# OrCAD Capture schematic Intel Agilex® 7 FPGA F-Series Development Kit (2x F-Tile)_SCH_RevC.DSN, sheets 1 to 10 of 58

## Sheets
1 PG01 COVER, TOC, NOTES: title: AGILEX FM86/FM76 DEVELOPMENT KIT; rev: C1; note: 180-0330678-C1
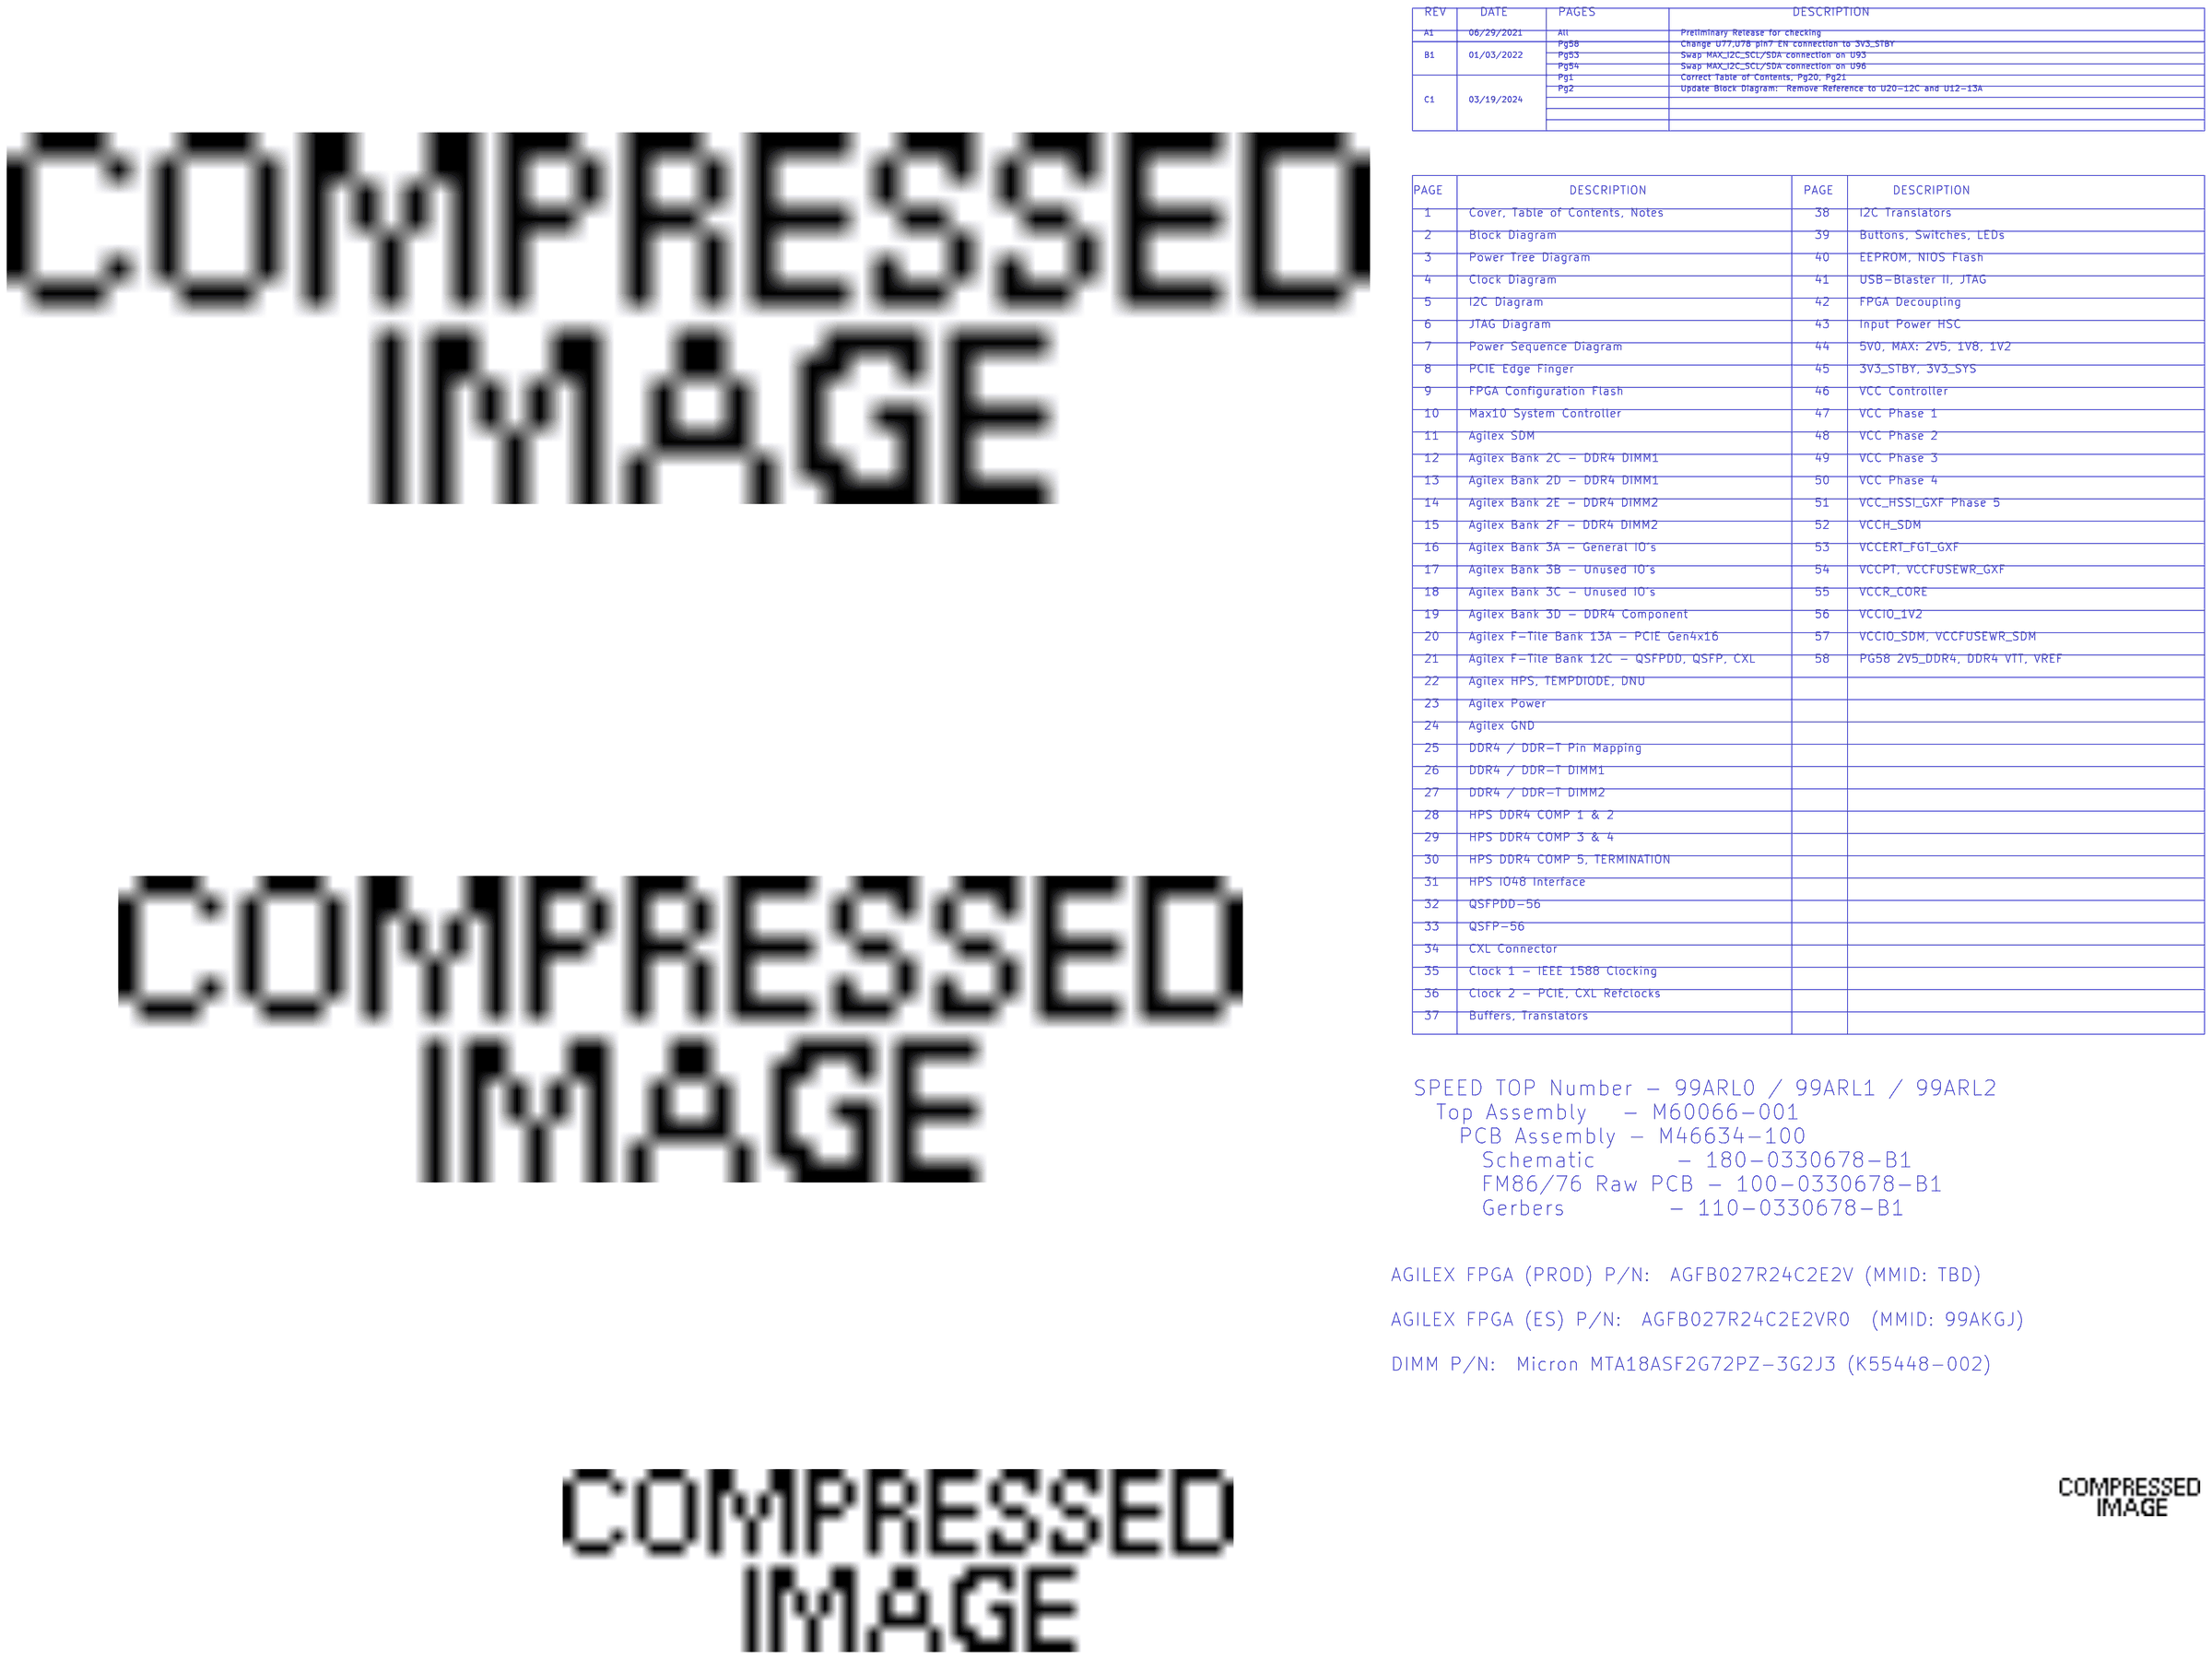
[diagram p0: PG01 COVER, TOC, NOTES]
2 PG02 BLOCK DIAGRAM
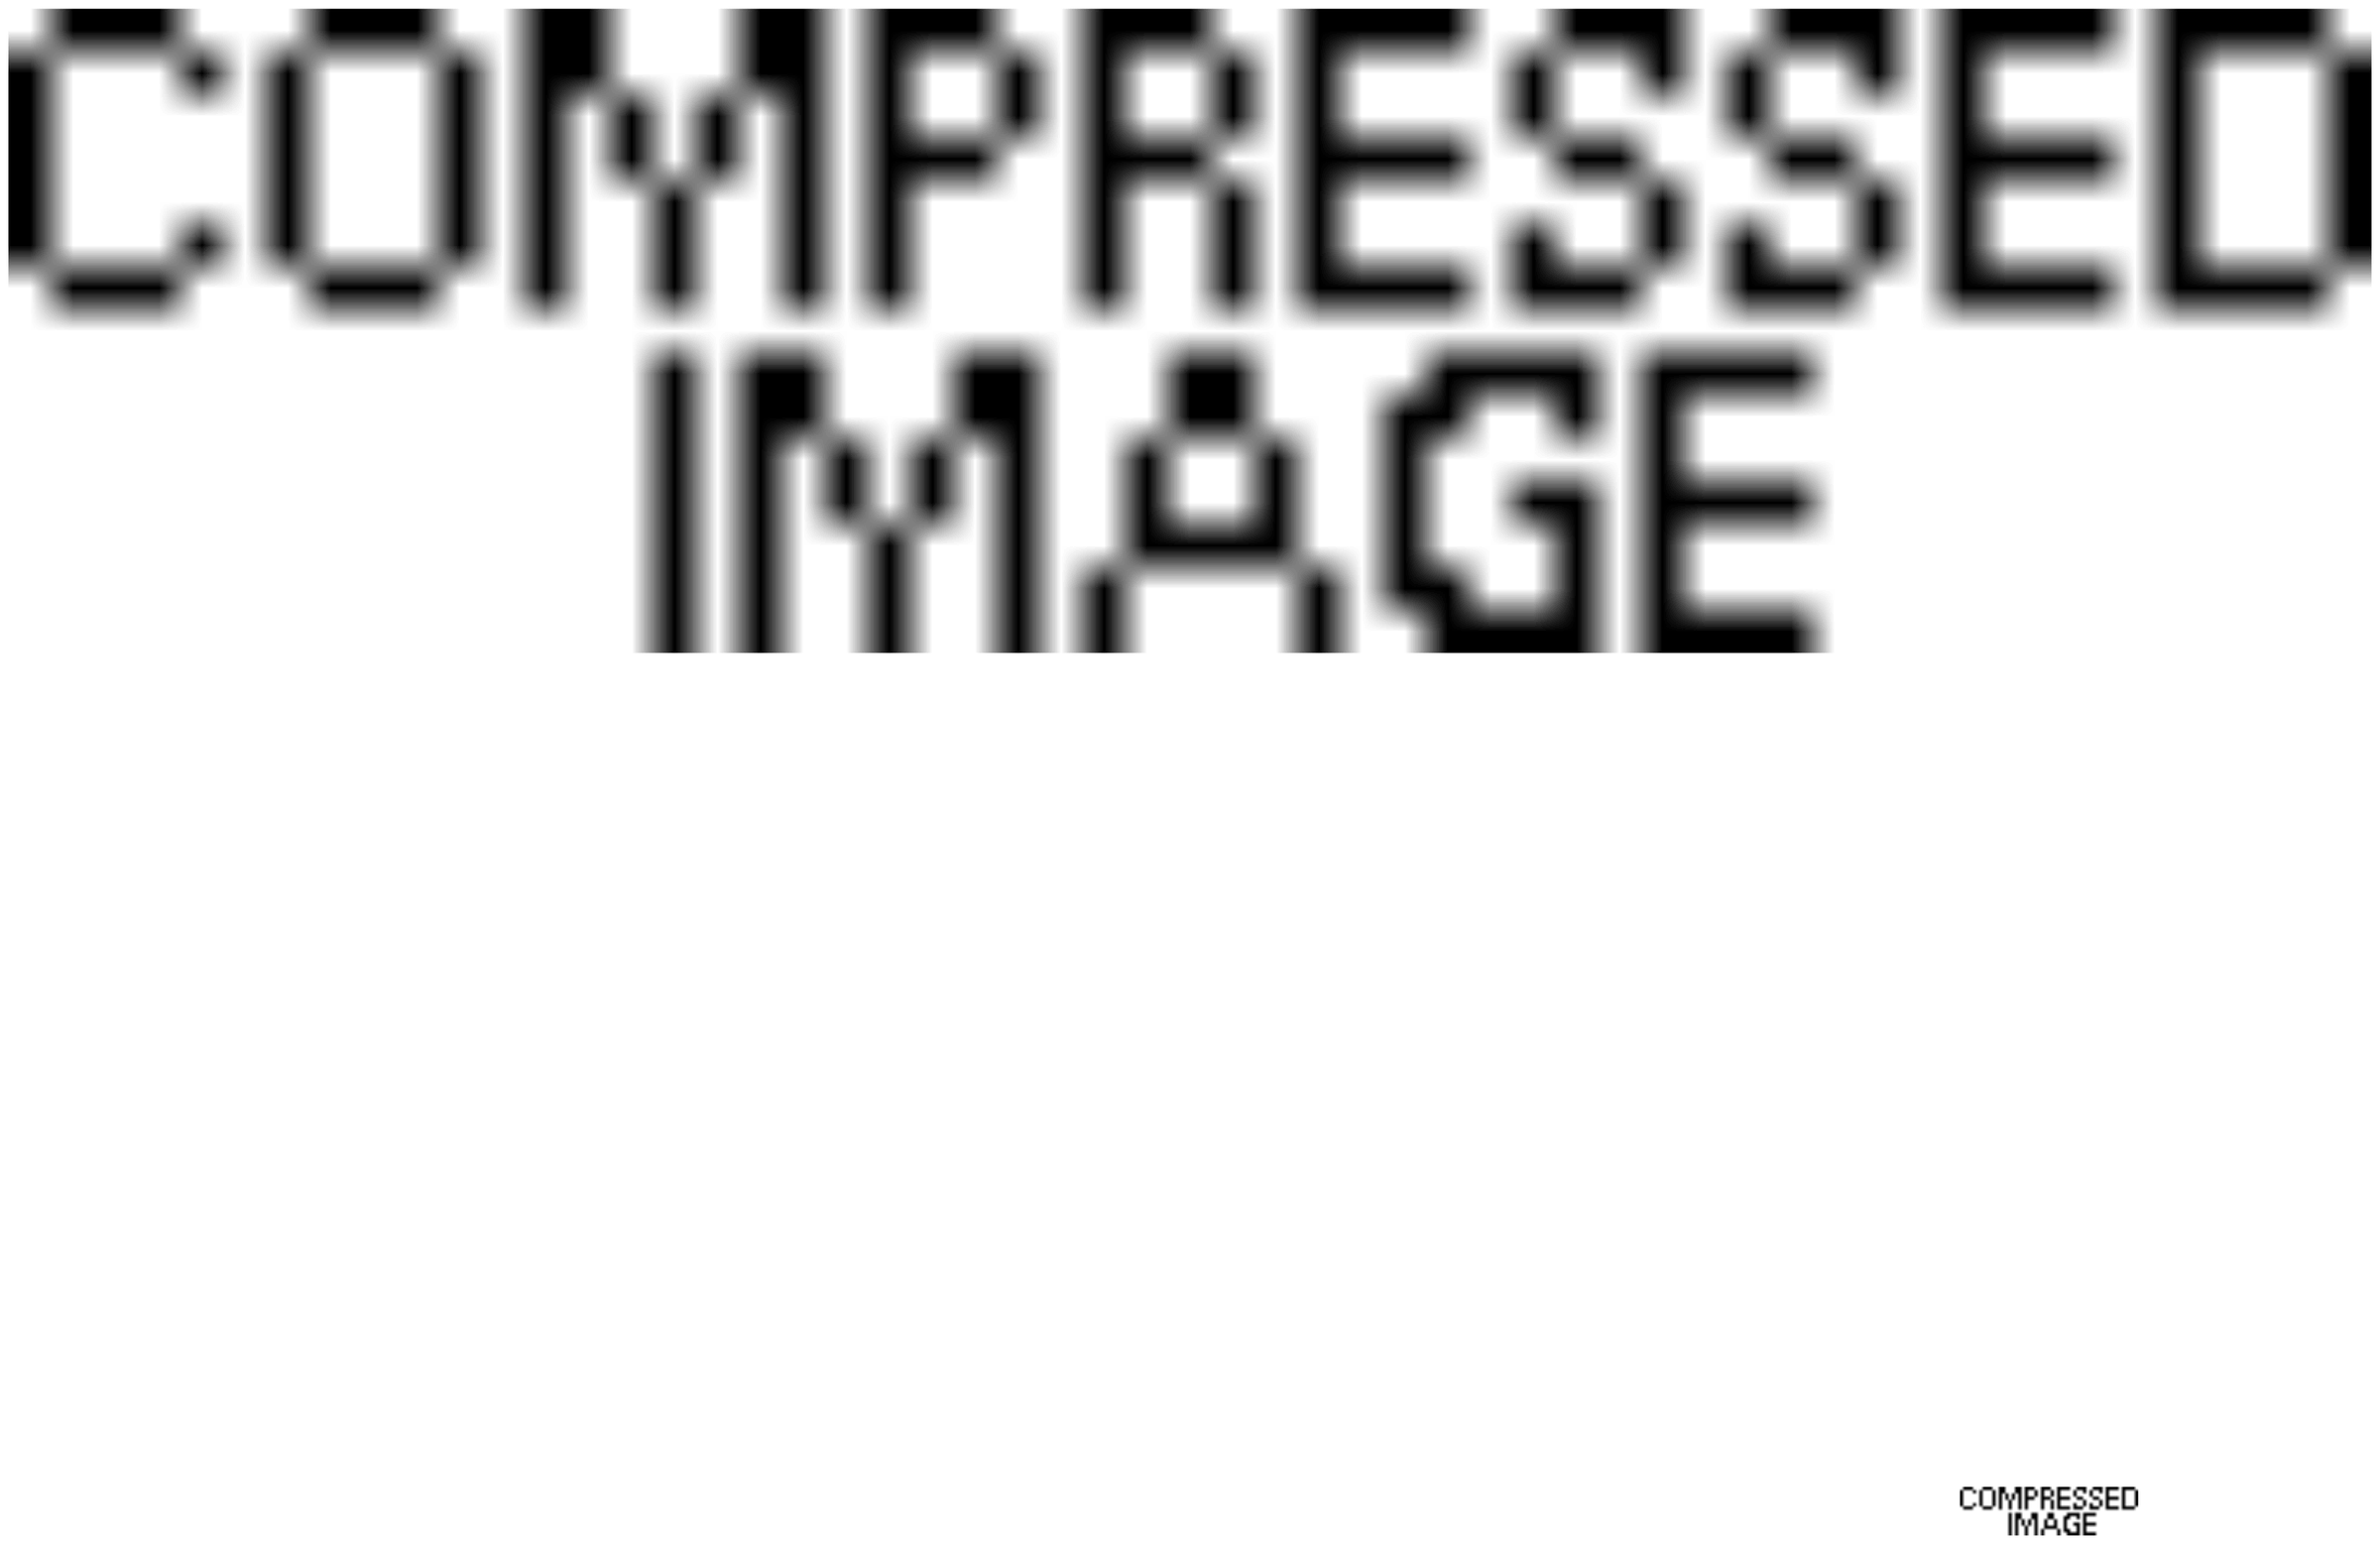
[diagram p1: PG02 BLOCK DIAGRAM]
3 PG03 POWER TREE DIAGRAM
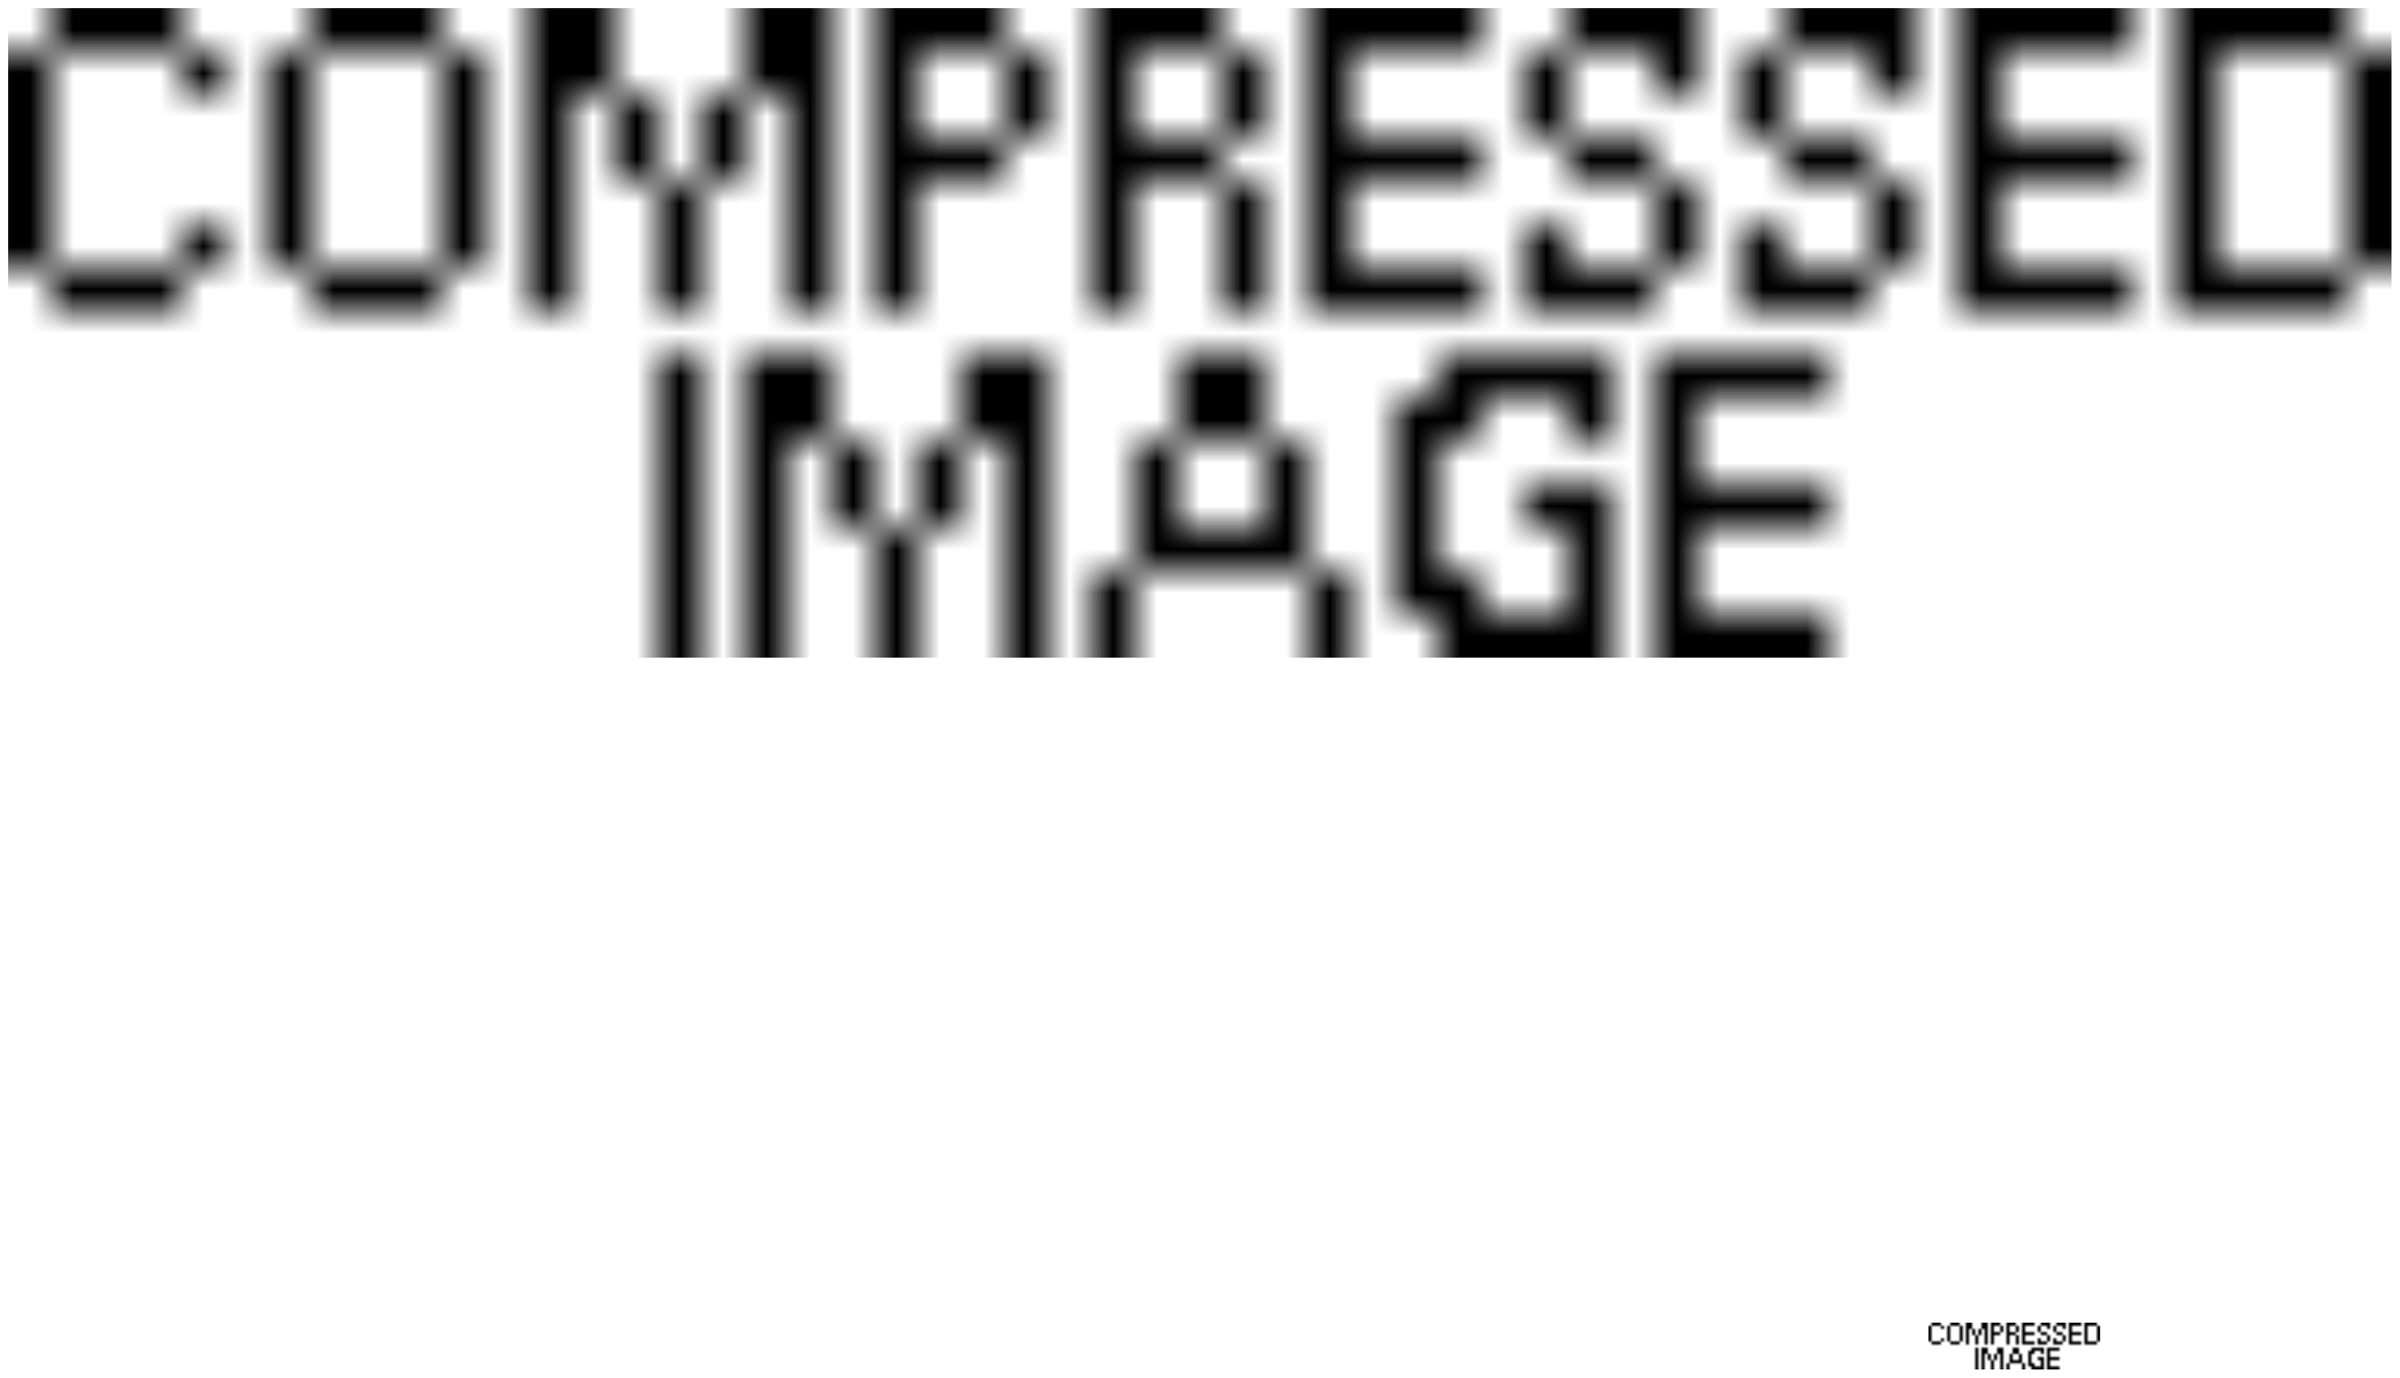
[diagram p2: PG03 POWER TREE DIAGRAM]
4 PG04 CLOCK DIAGRAM
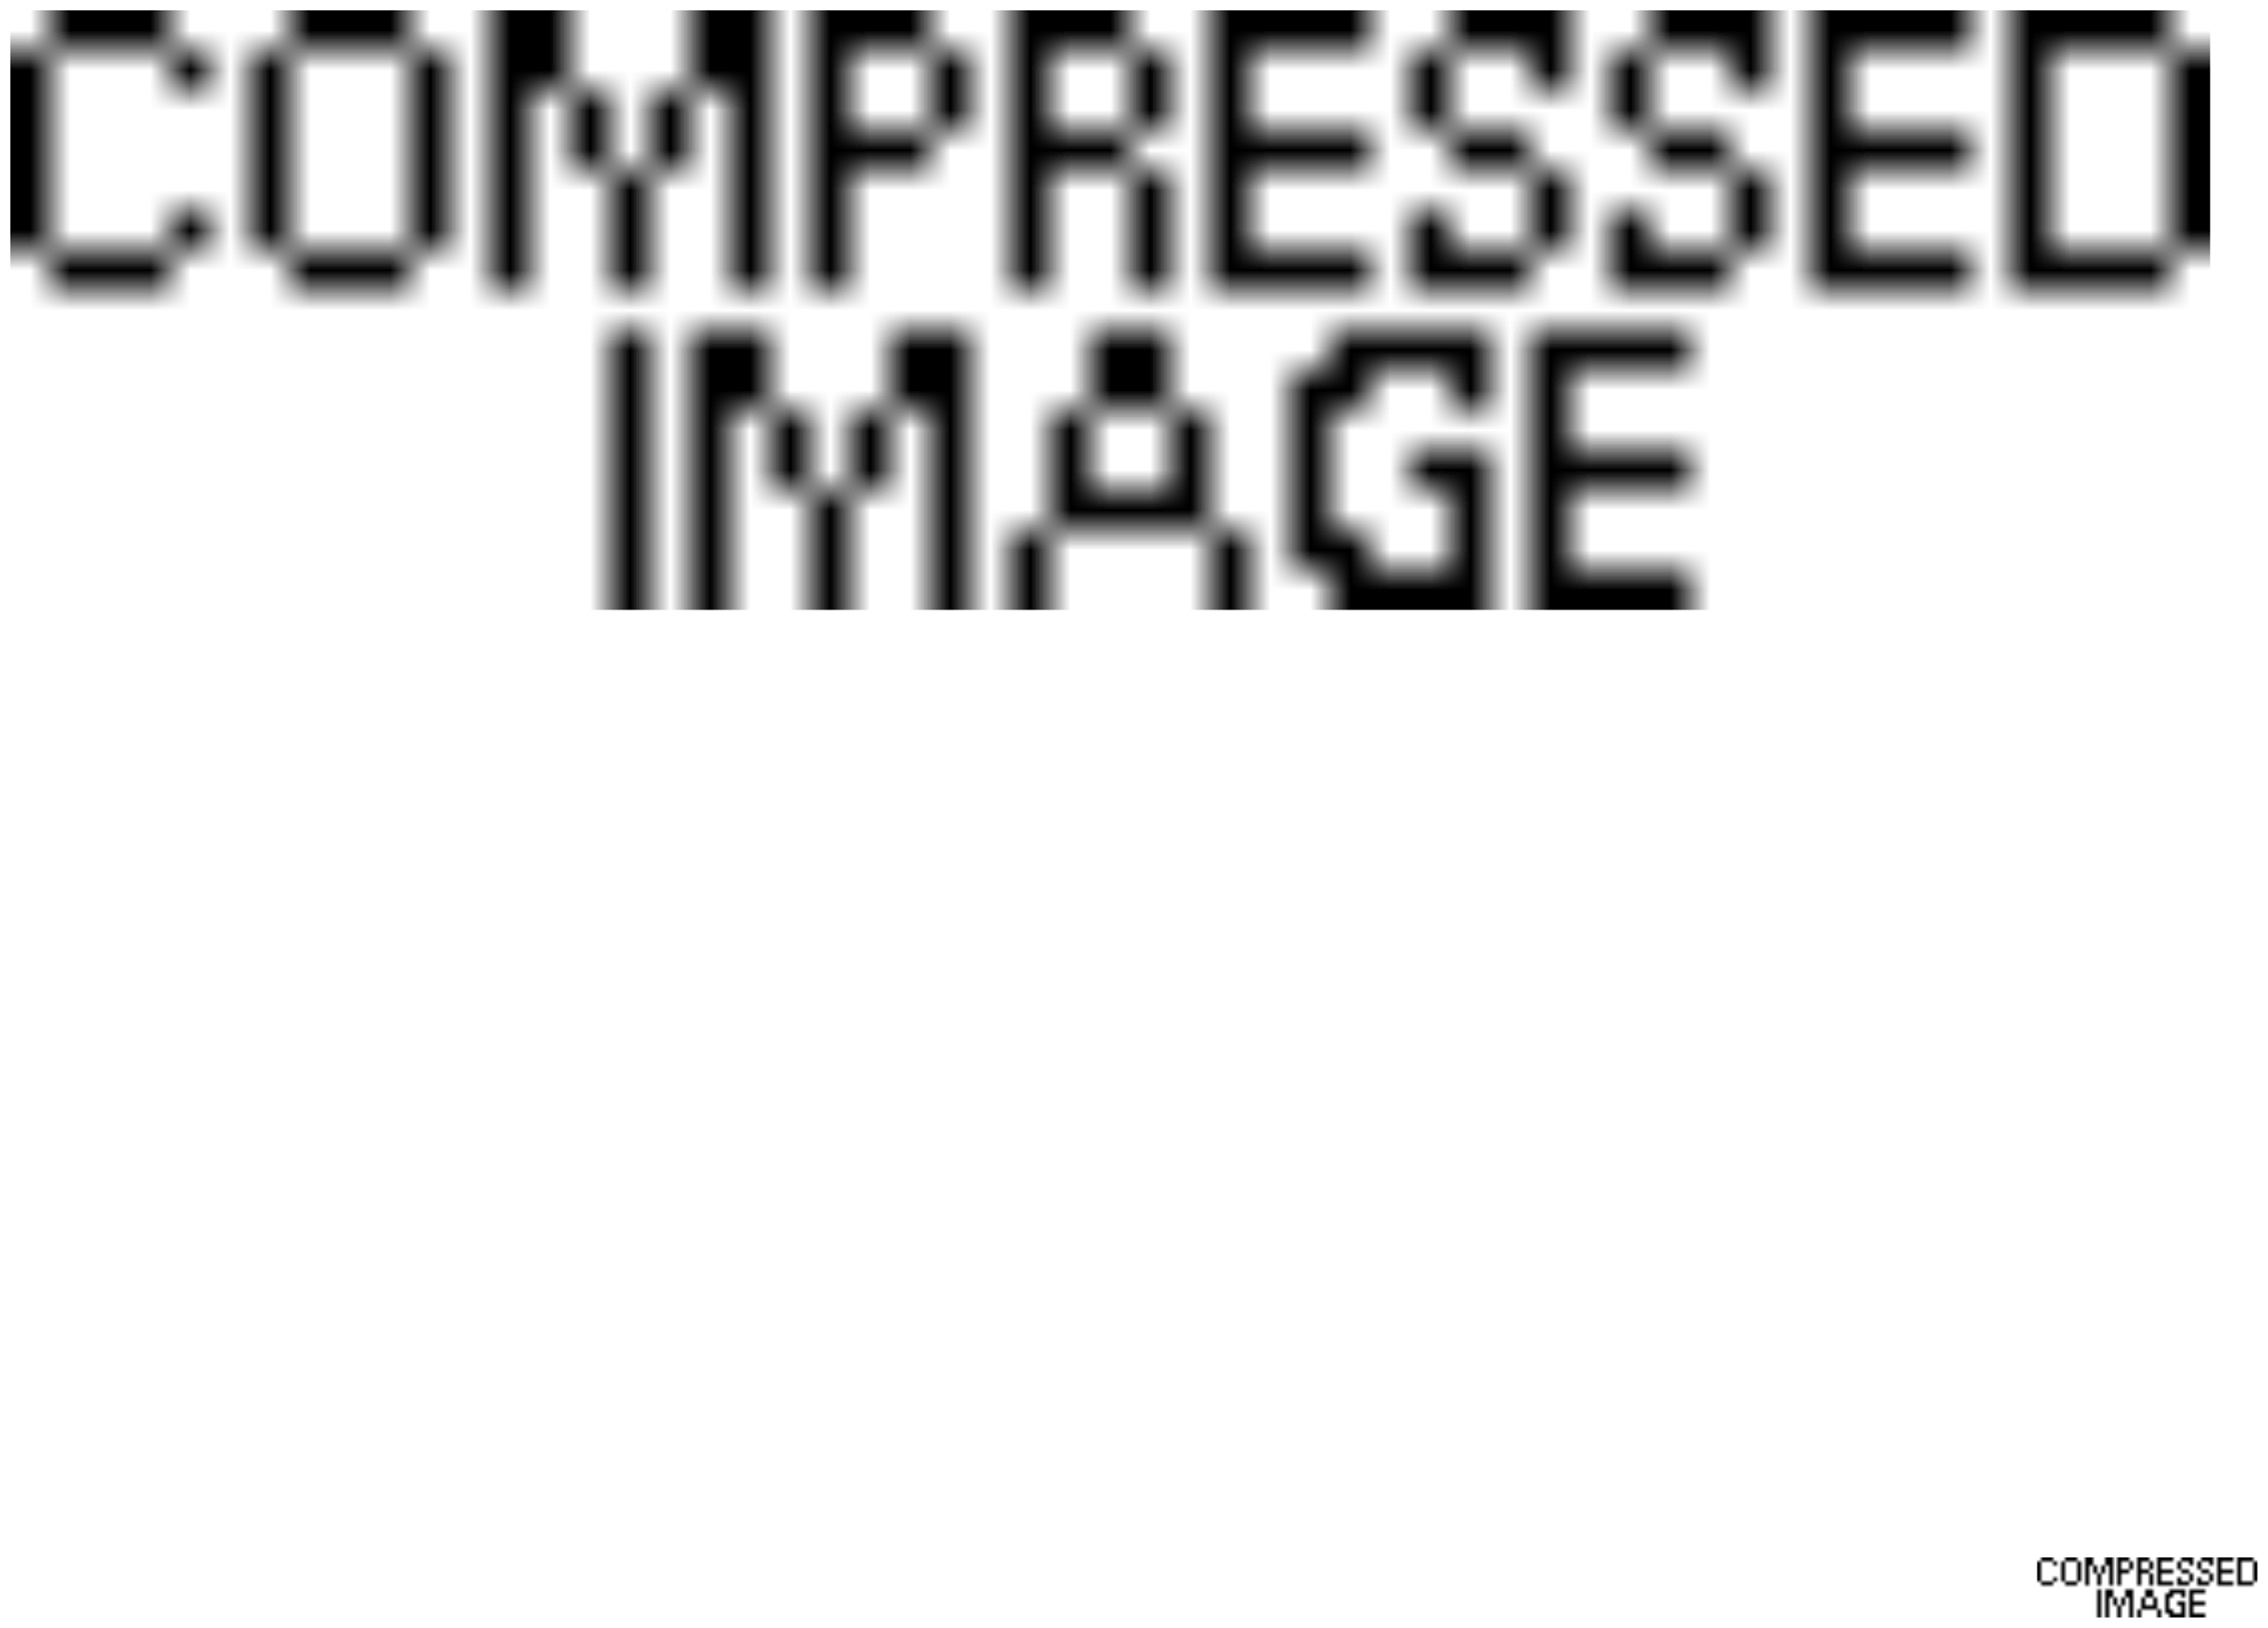
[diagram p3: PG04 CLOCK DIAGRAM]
5 PG05 I2C DIAGRAM
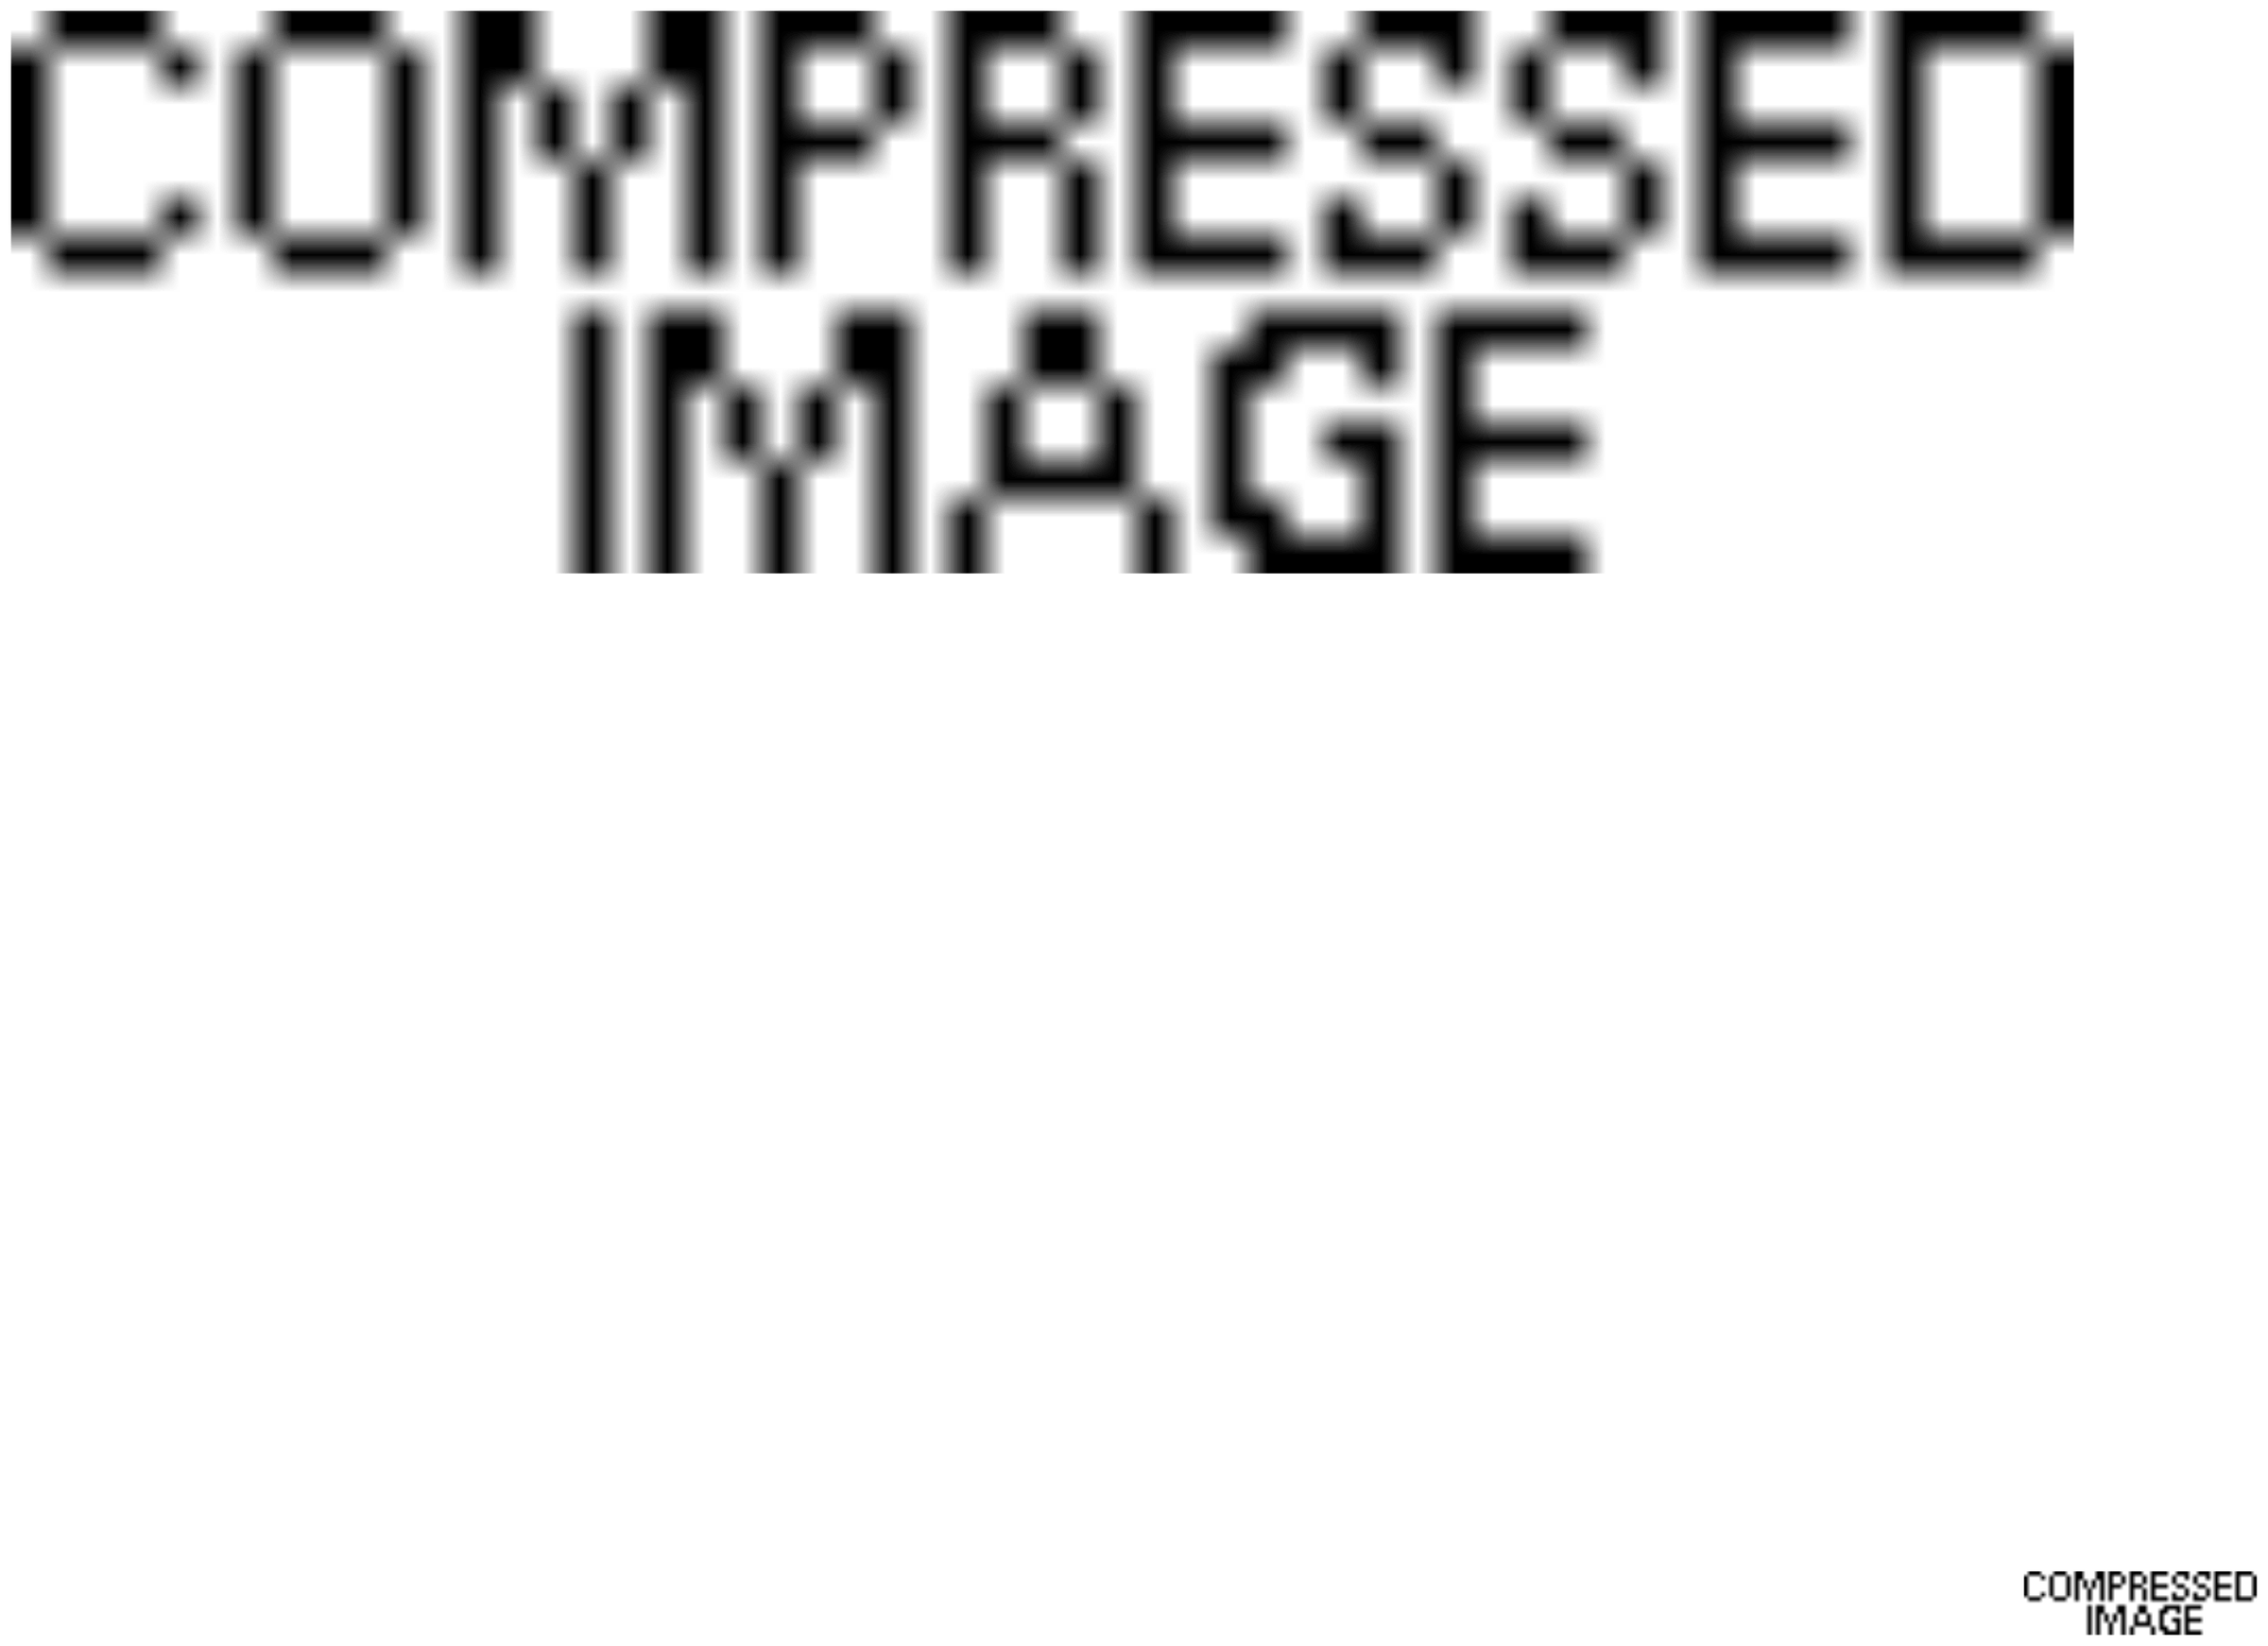
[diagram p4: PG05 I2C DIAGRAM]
6 PG06 JTAG & PCIE RESET DIAGRAM
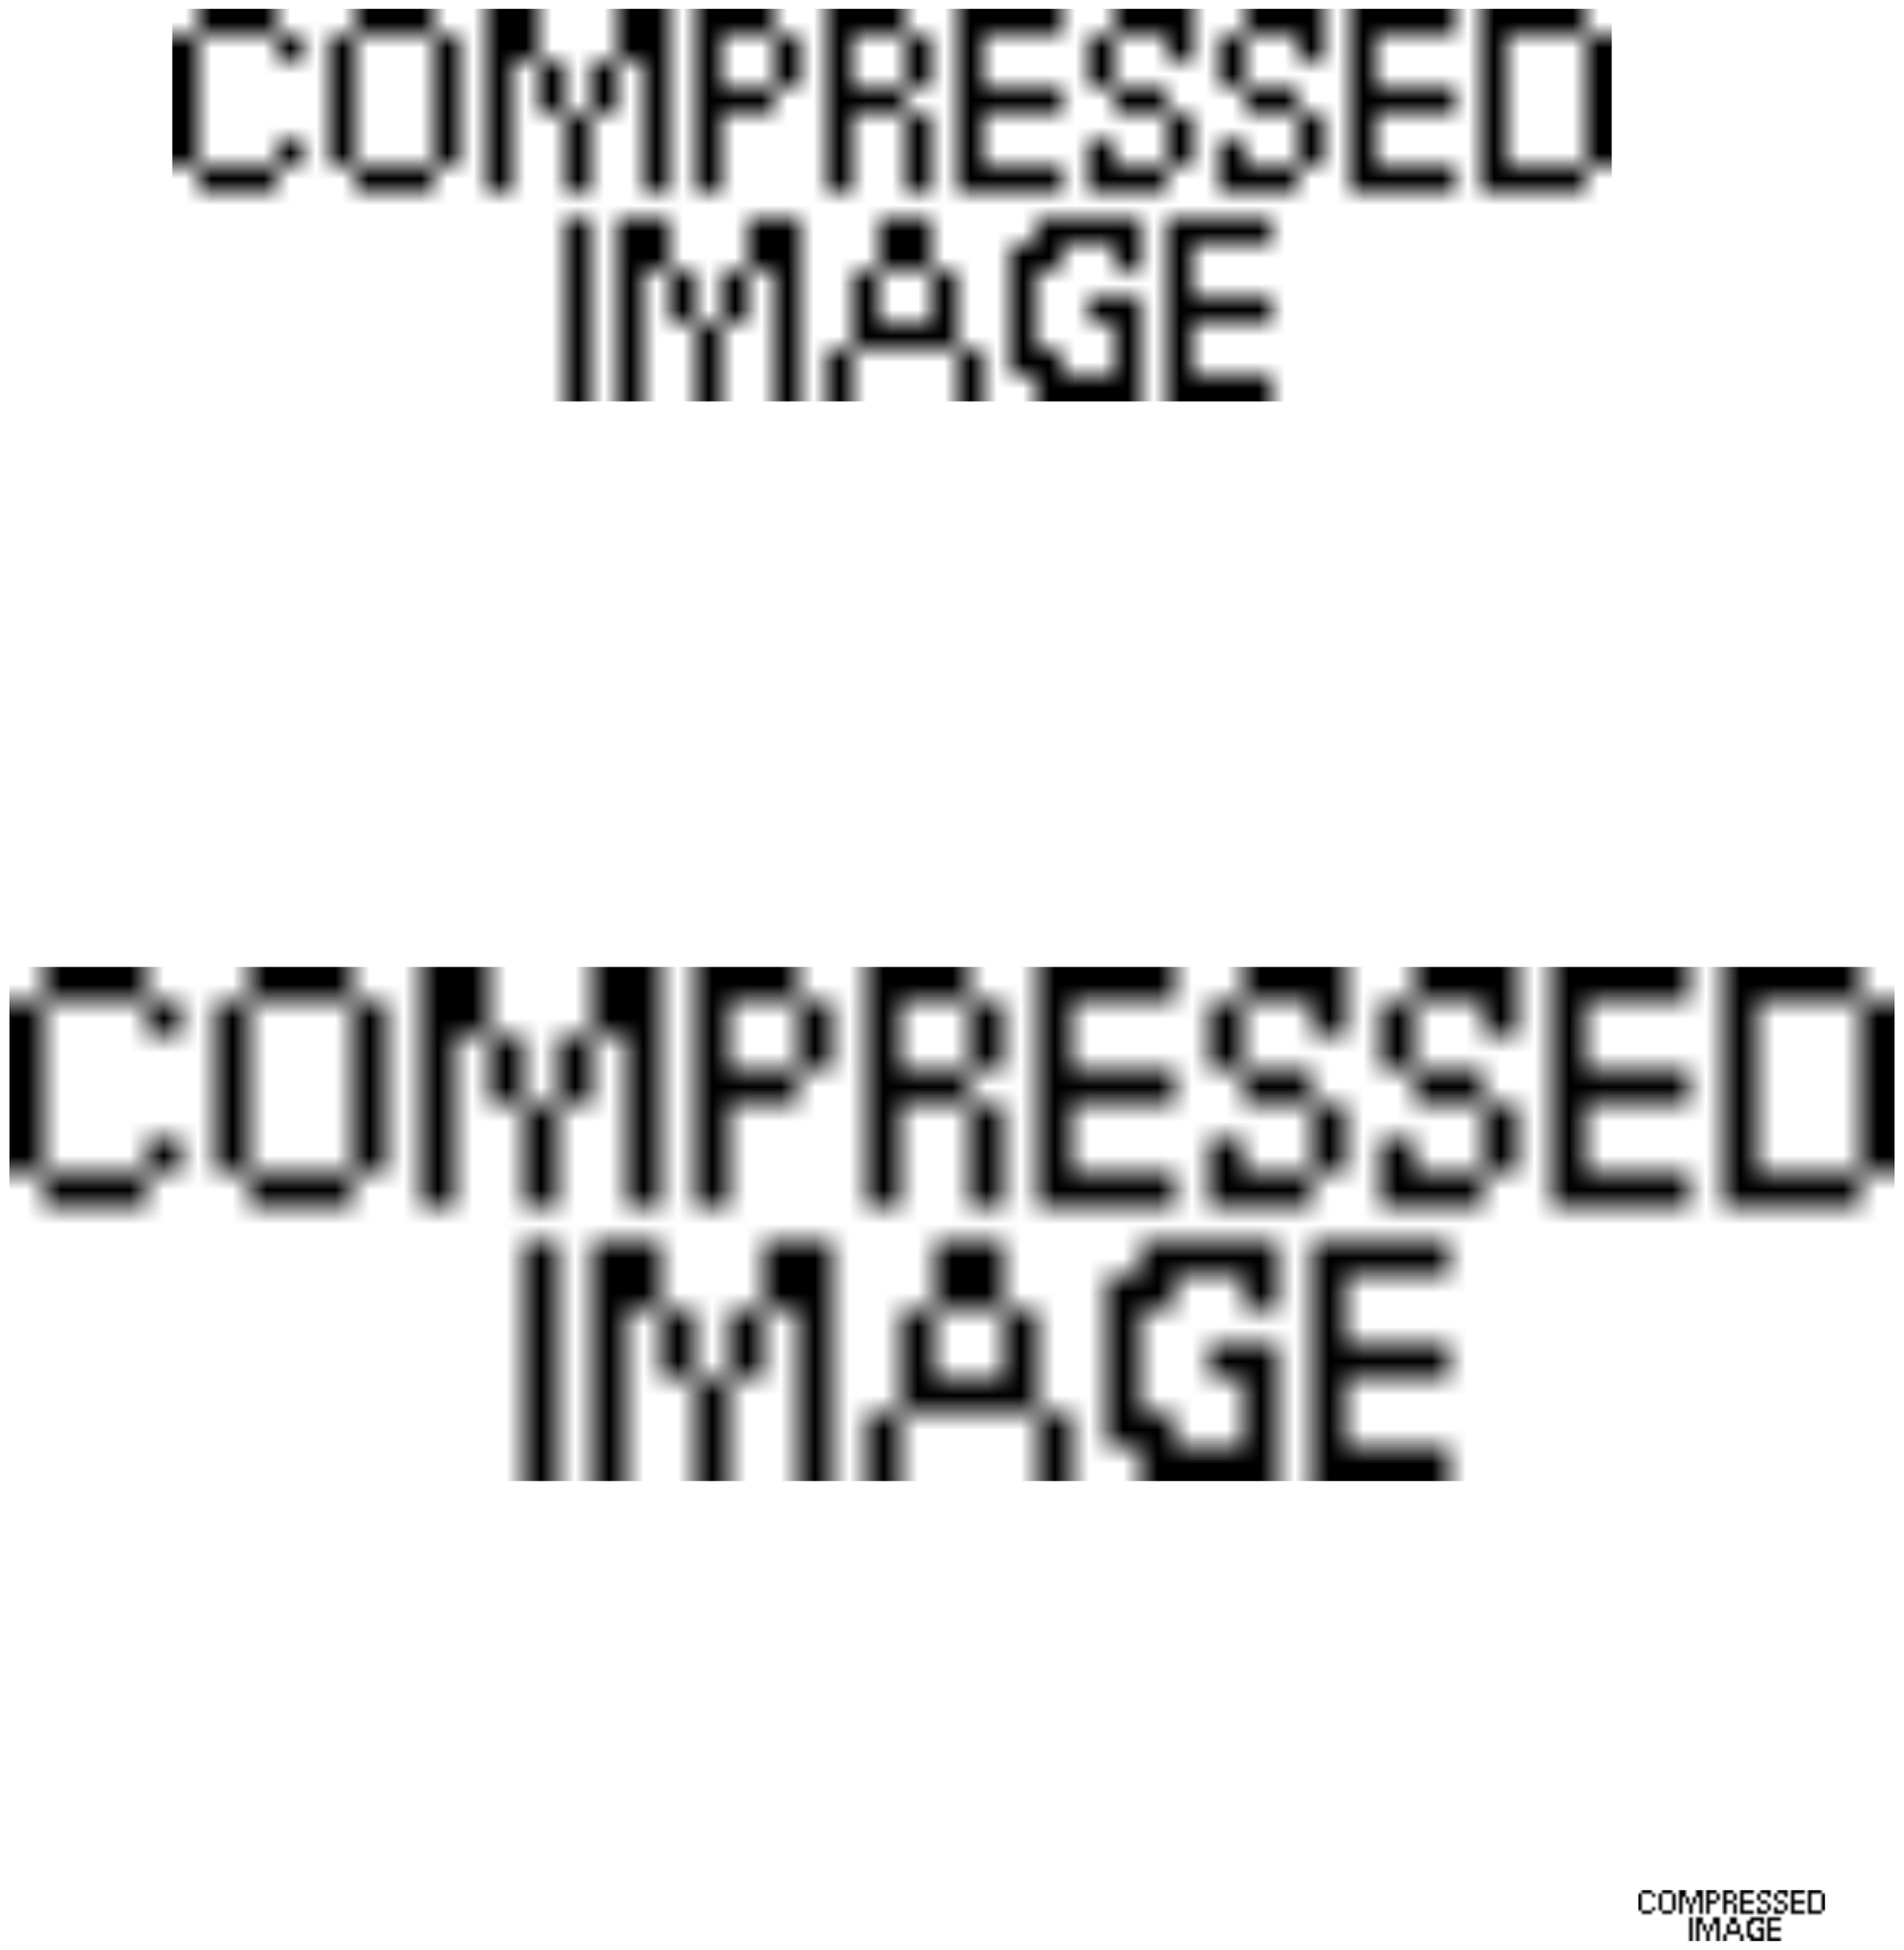
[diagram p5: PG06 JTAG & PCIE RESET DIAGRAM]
7 PG07 MAX10 CONTROLLER DIAGRAM
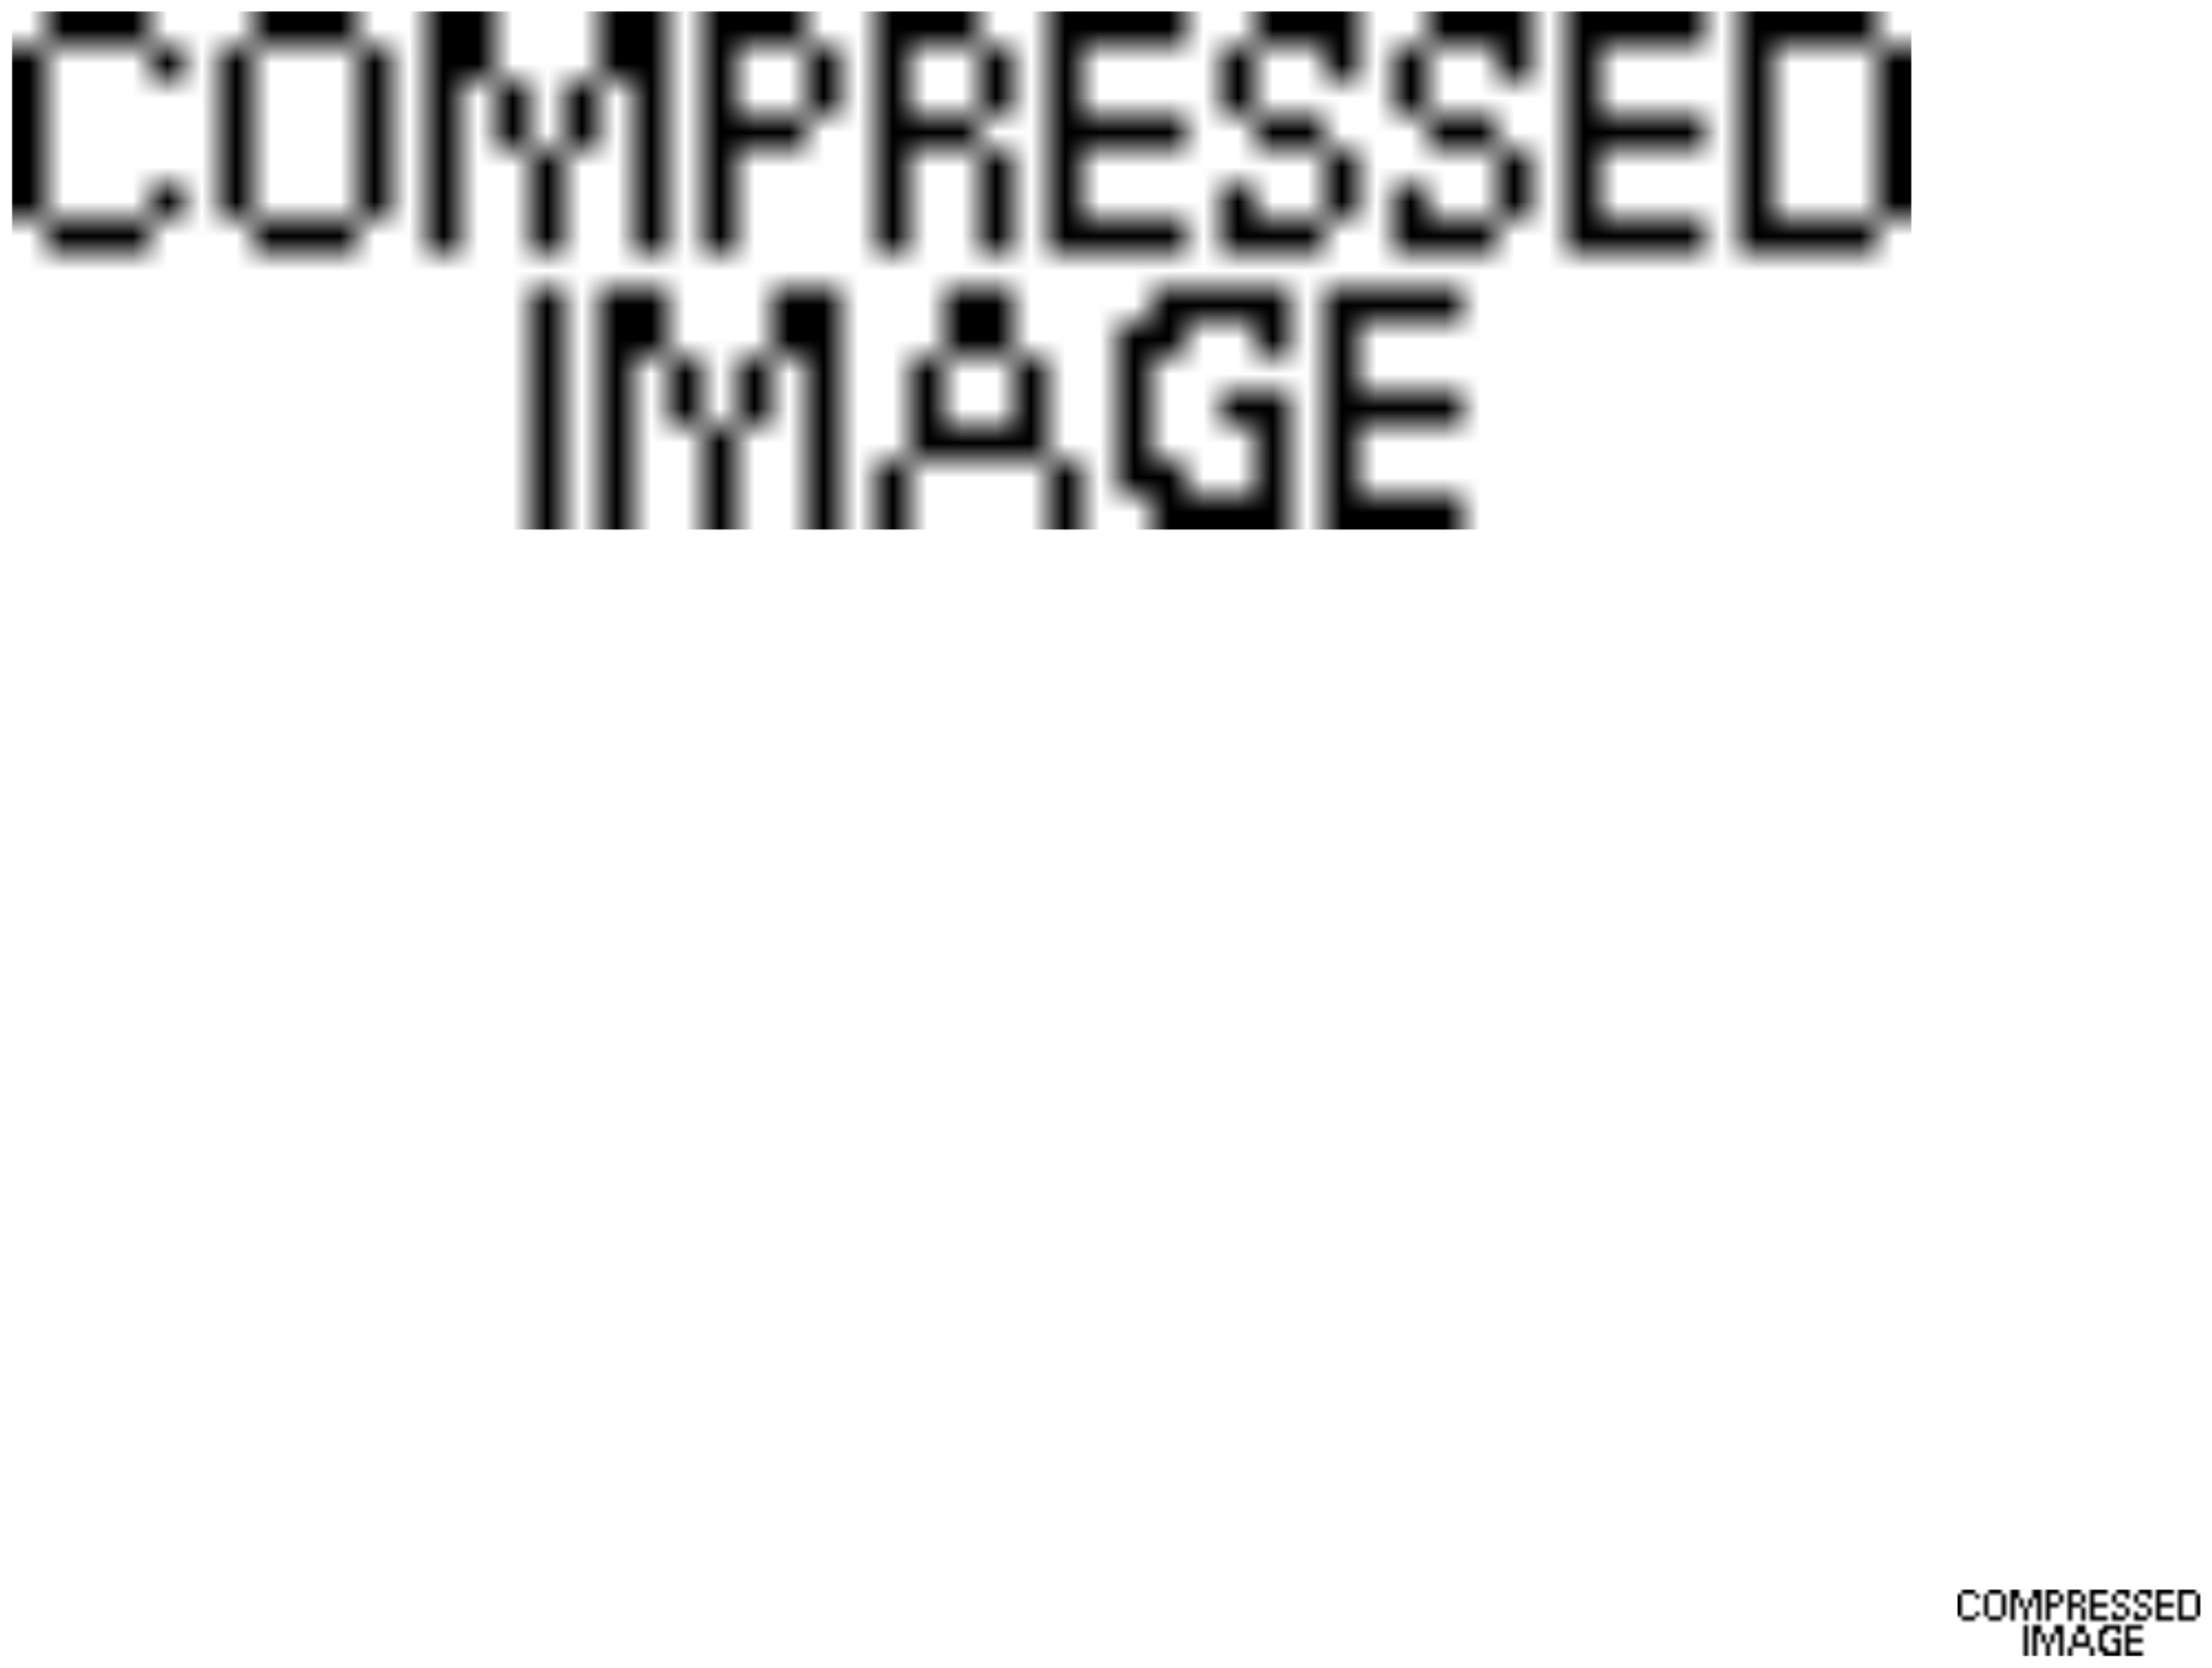
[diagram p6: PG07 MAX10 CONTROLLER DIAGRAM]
8 PG08 PCIE EDGE FINGER: size C
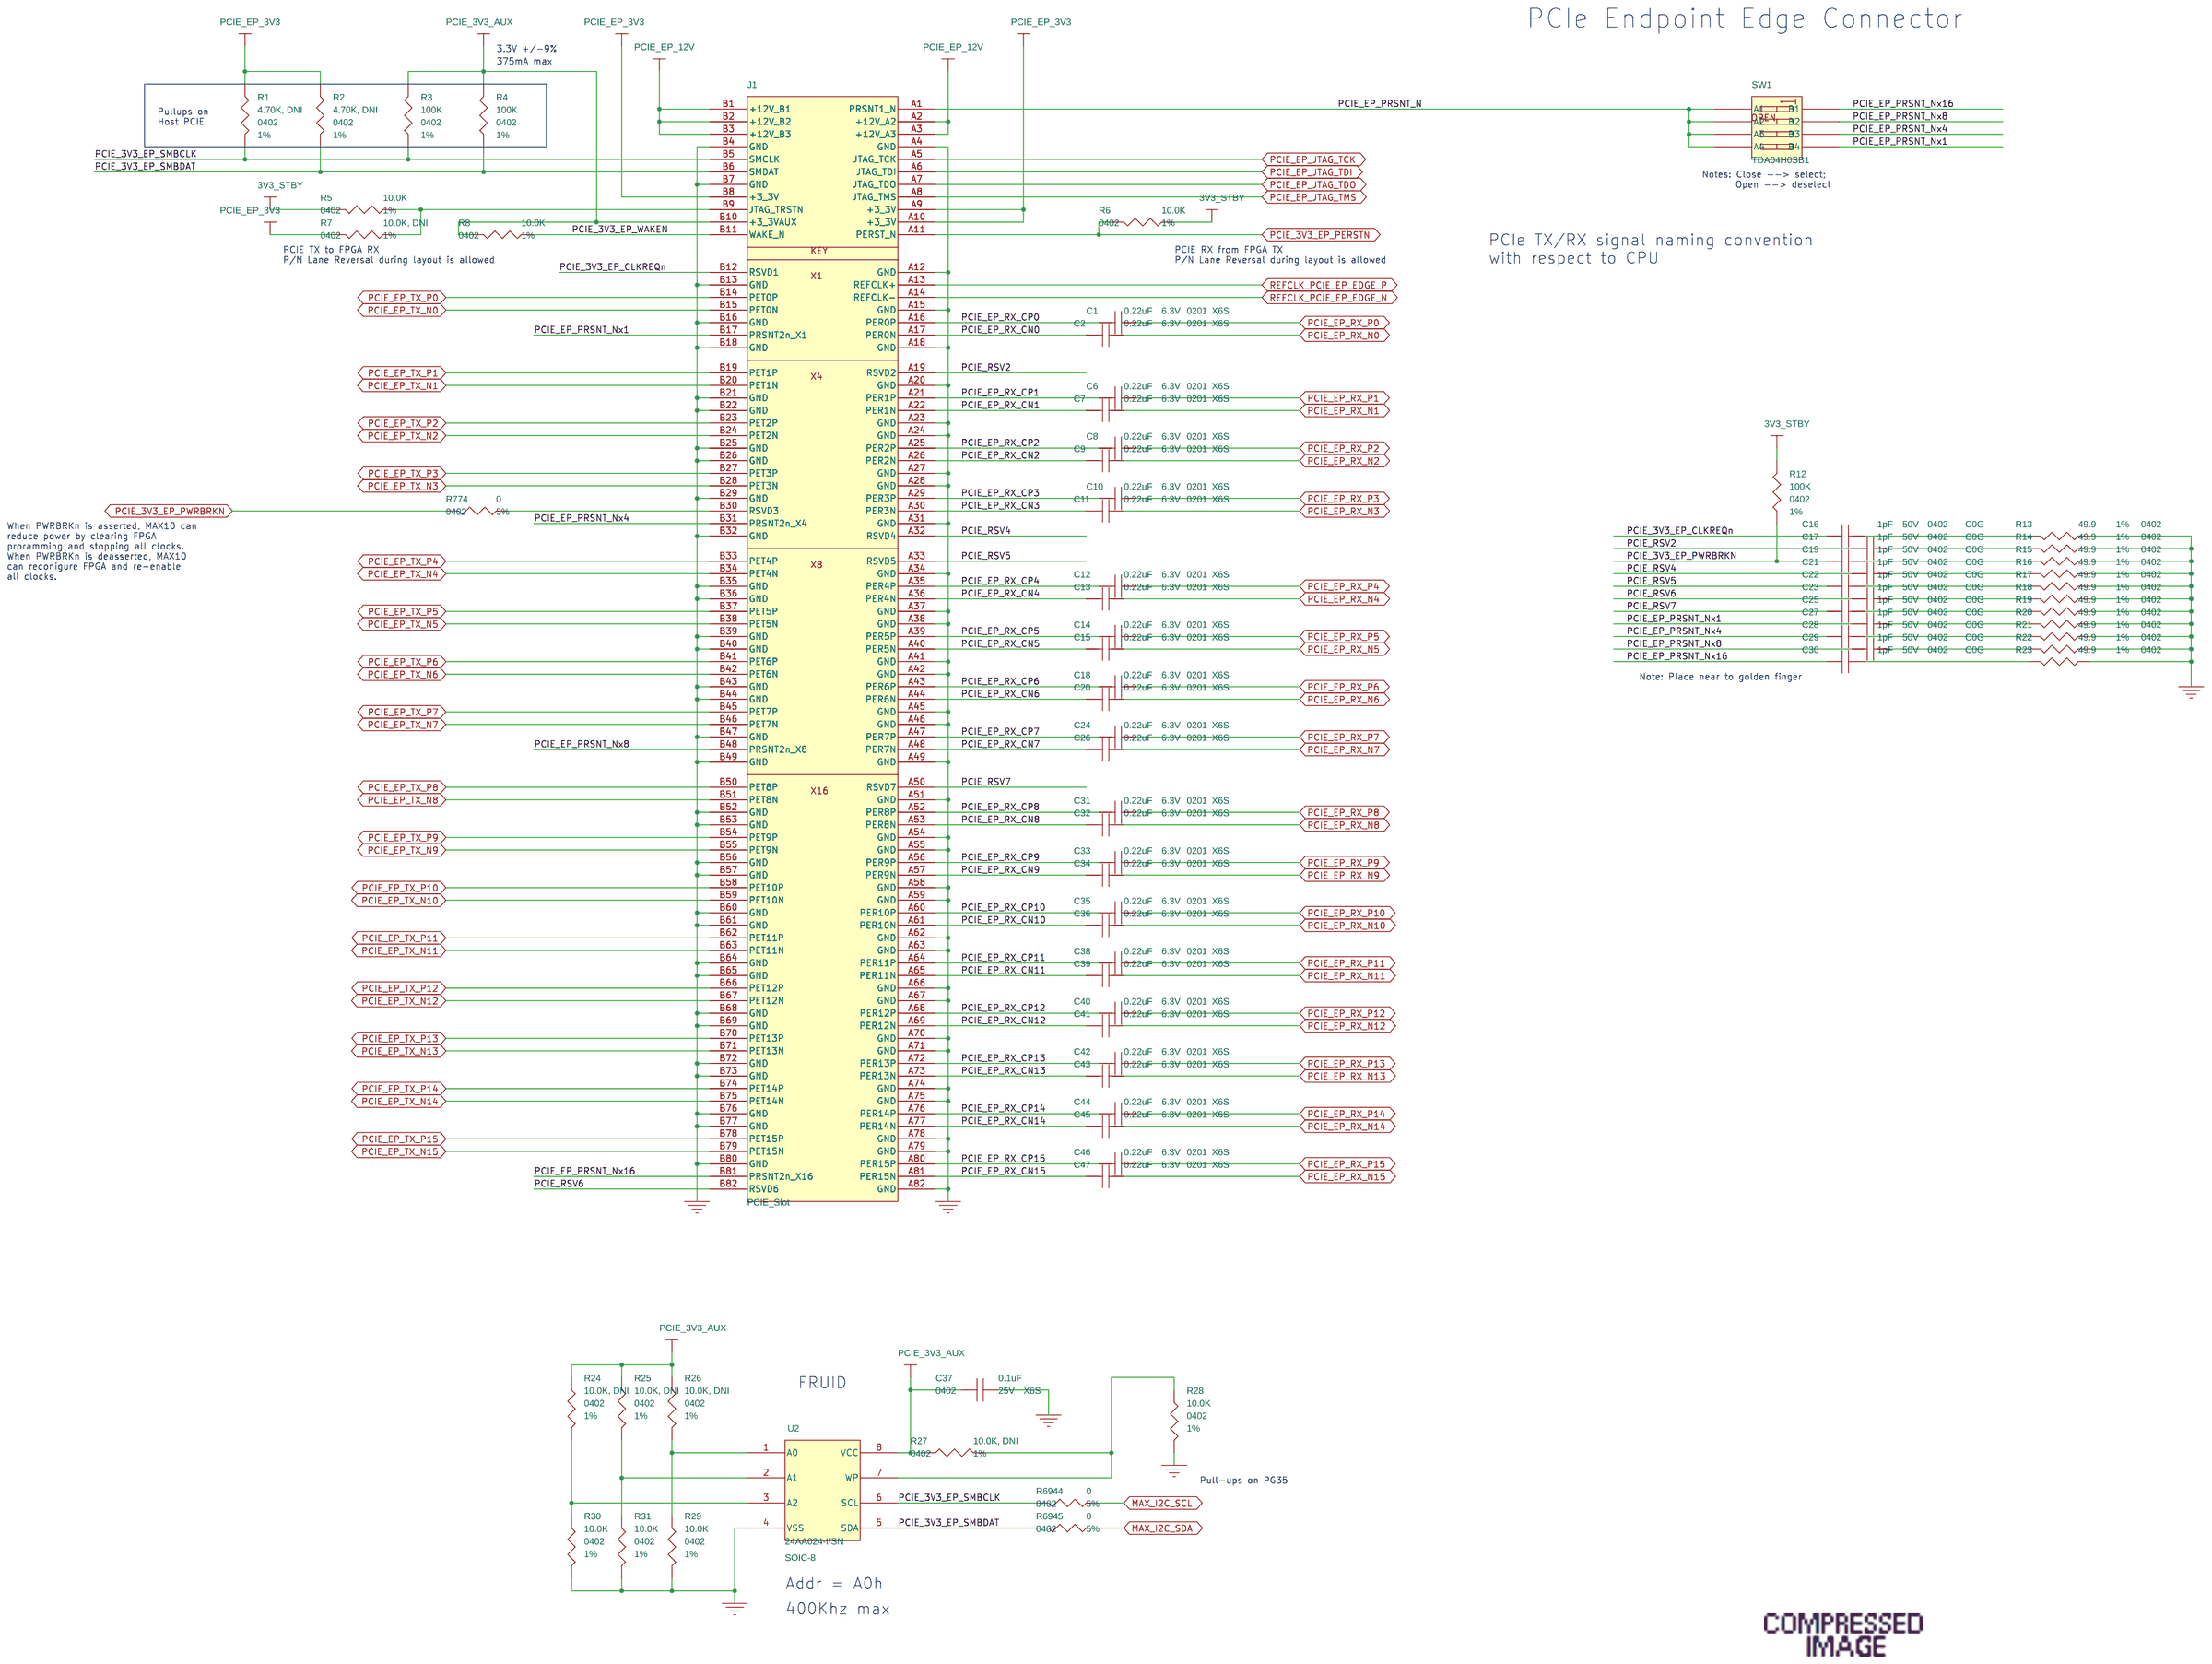
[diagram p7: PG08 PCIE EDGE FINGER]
9 PG09 FPGA CONFIG FLASH: size C
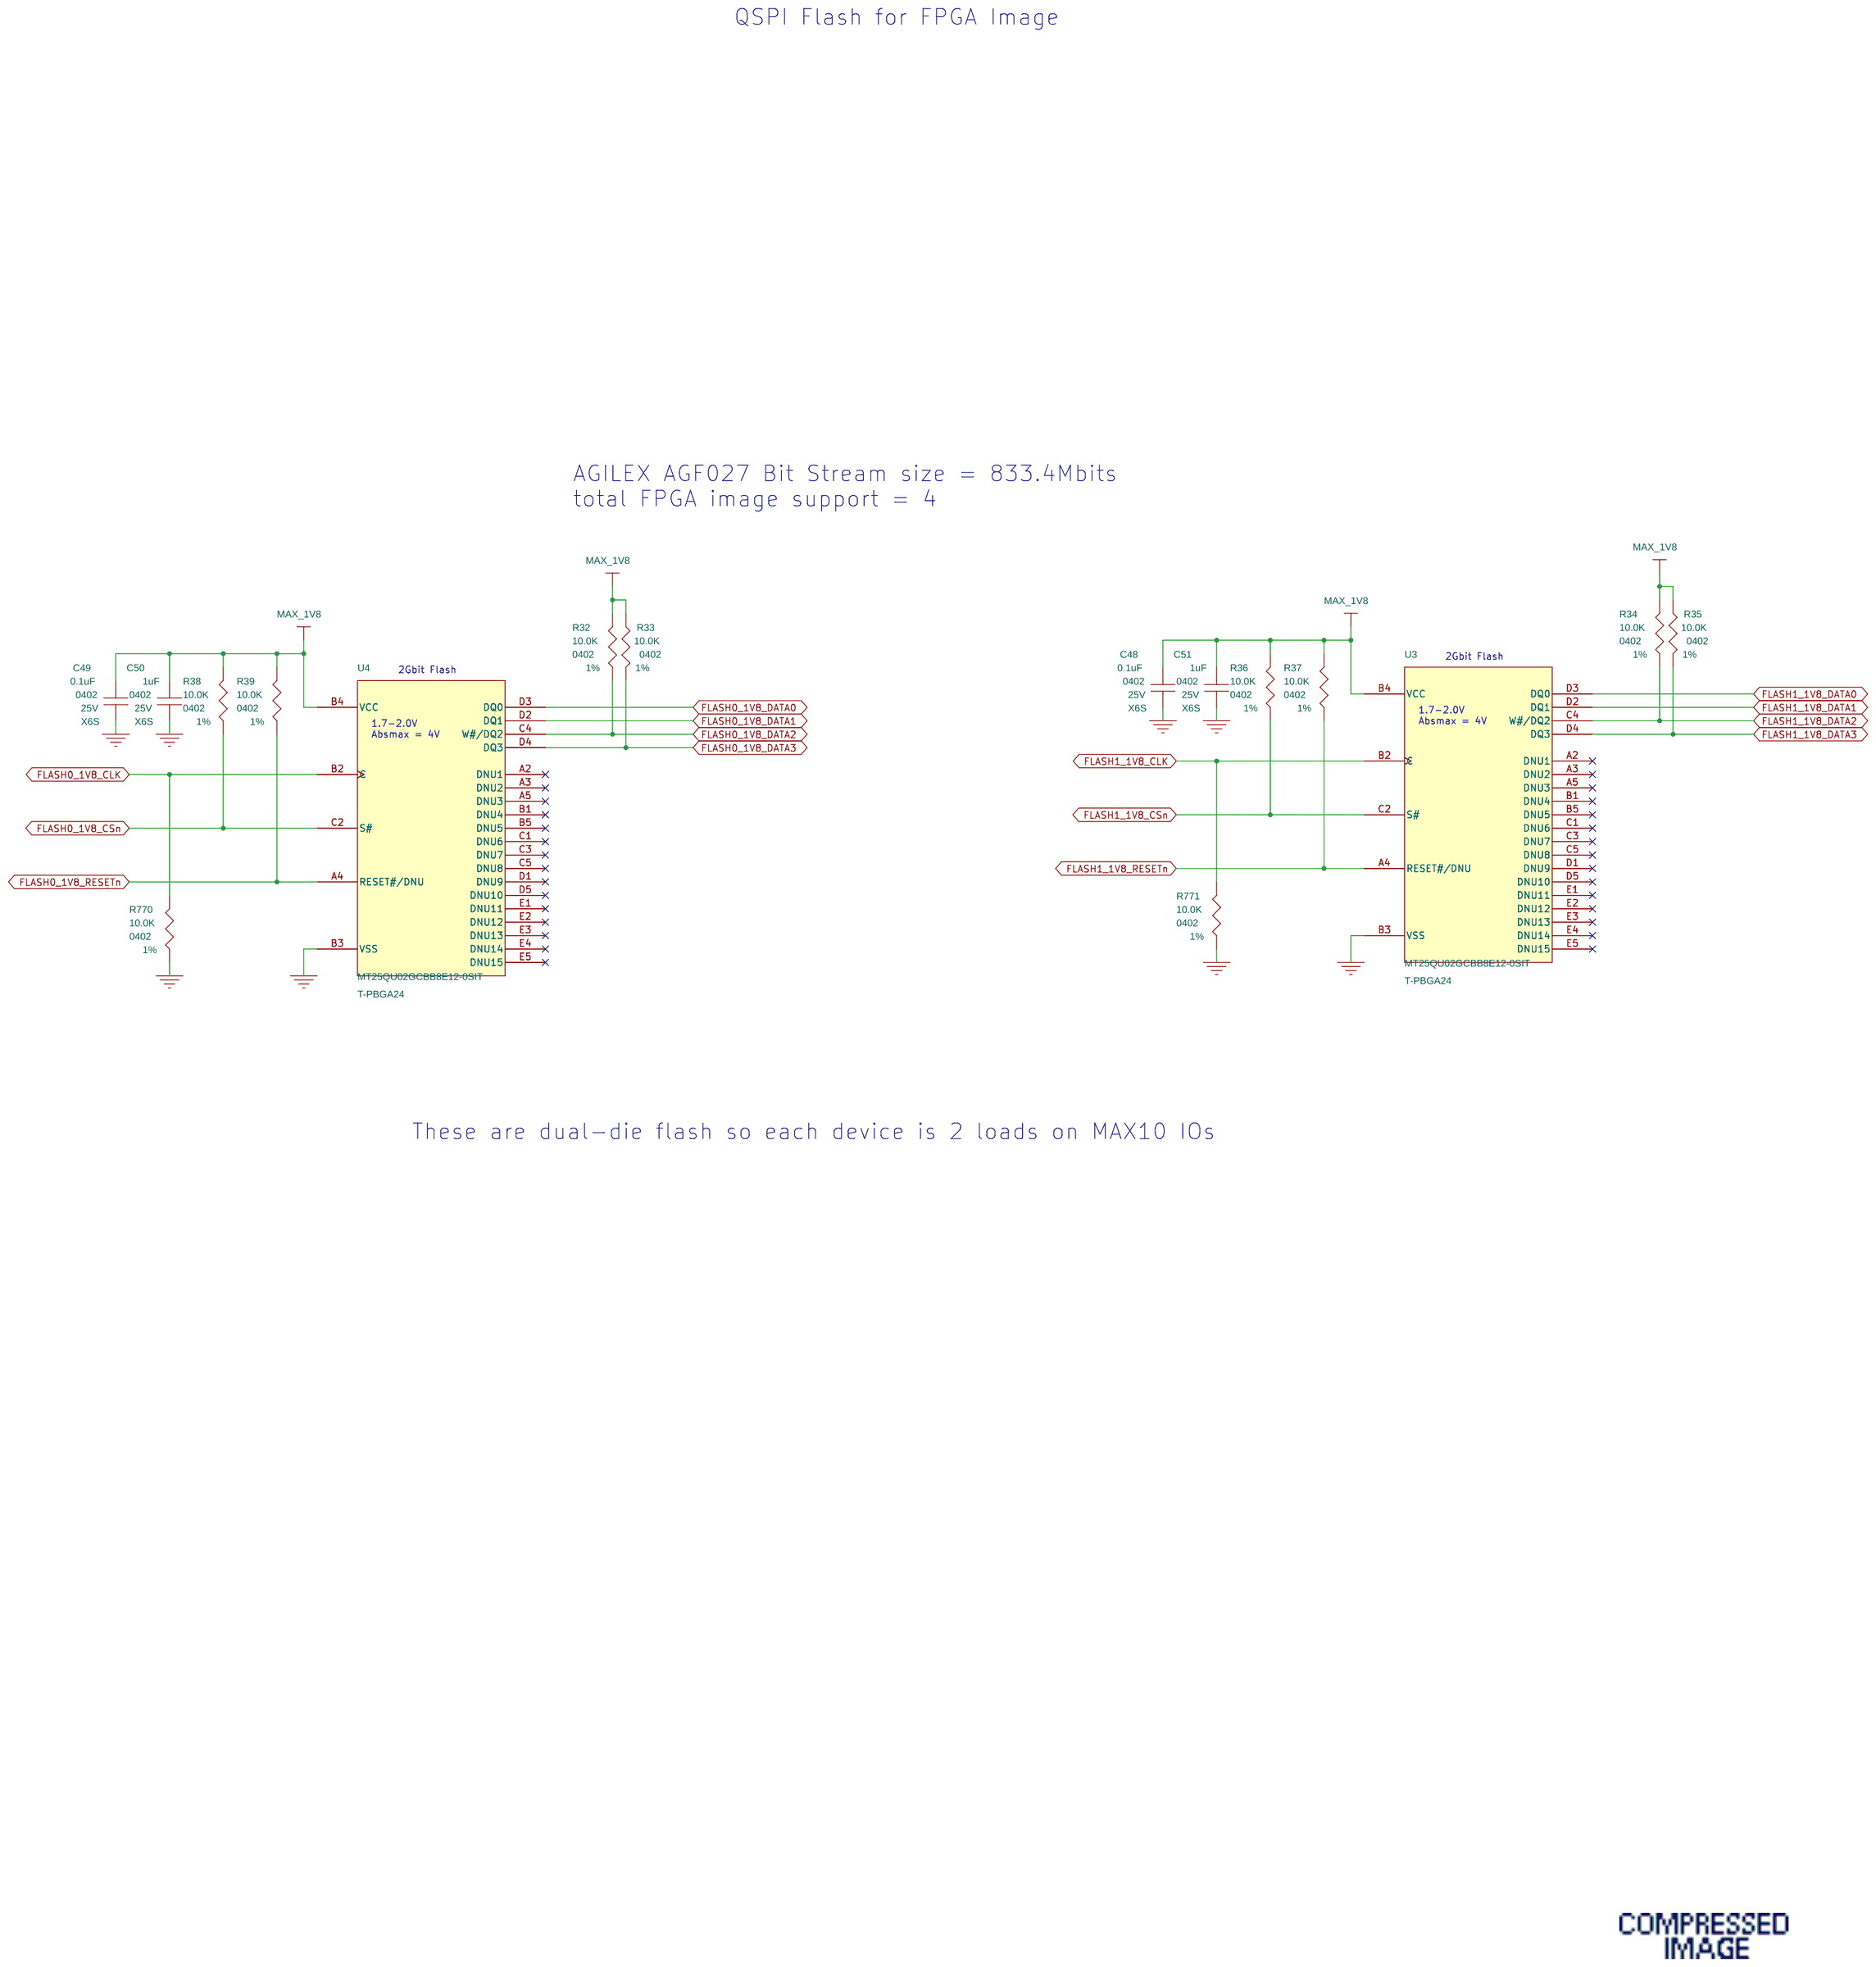
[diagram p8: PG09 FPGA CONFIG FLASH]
10 PG10 MAX10 SYSTEM CTRL: size C
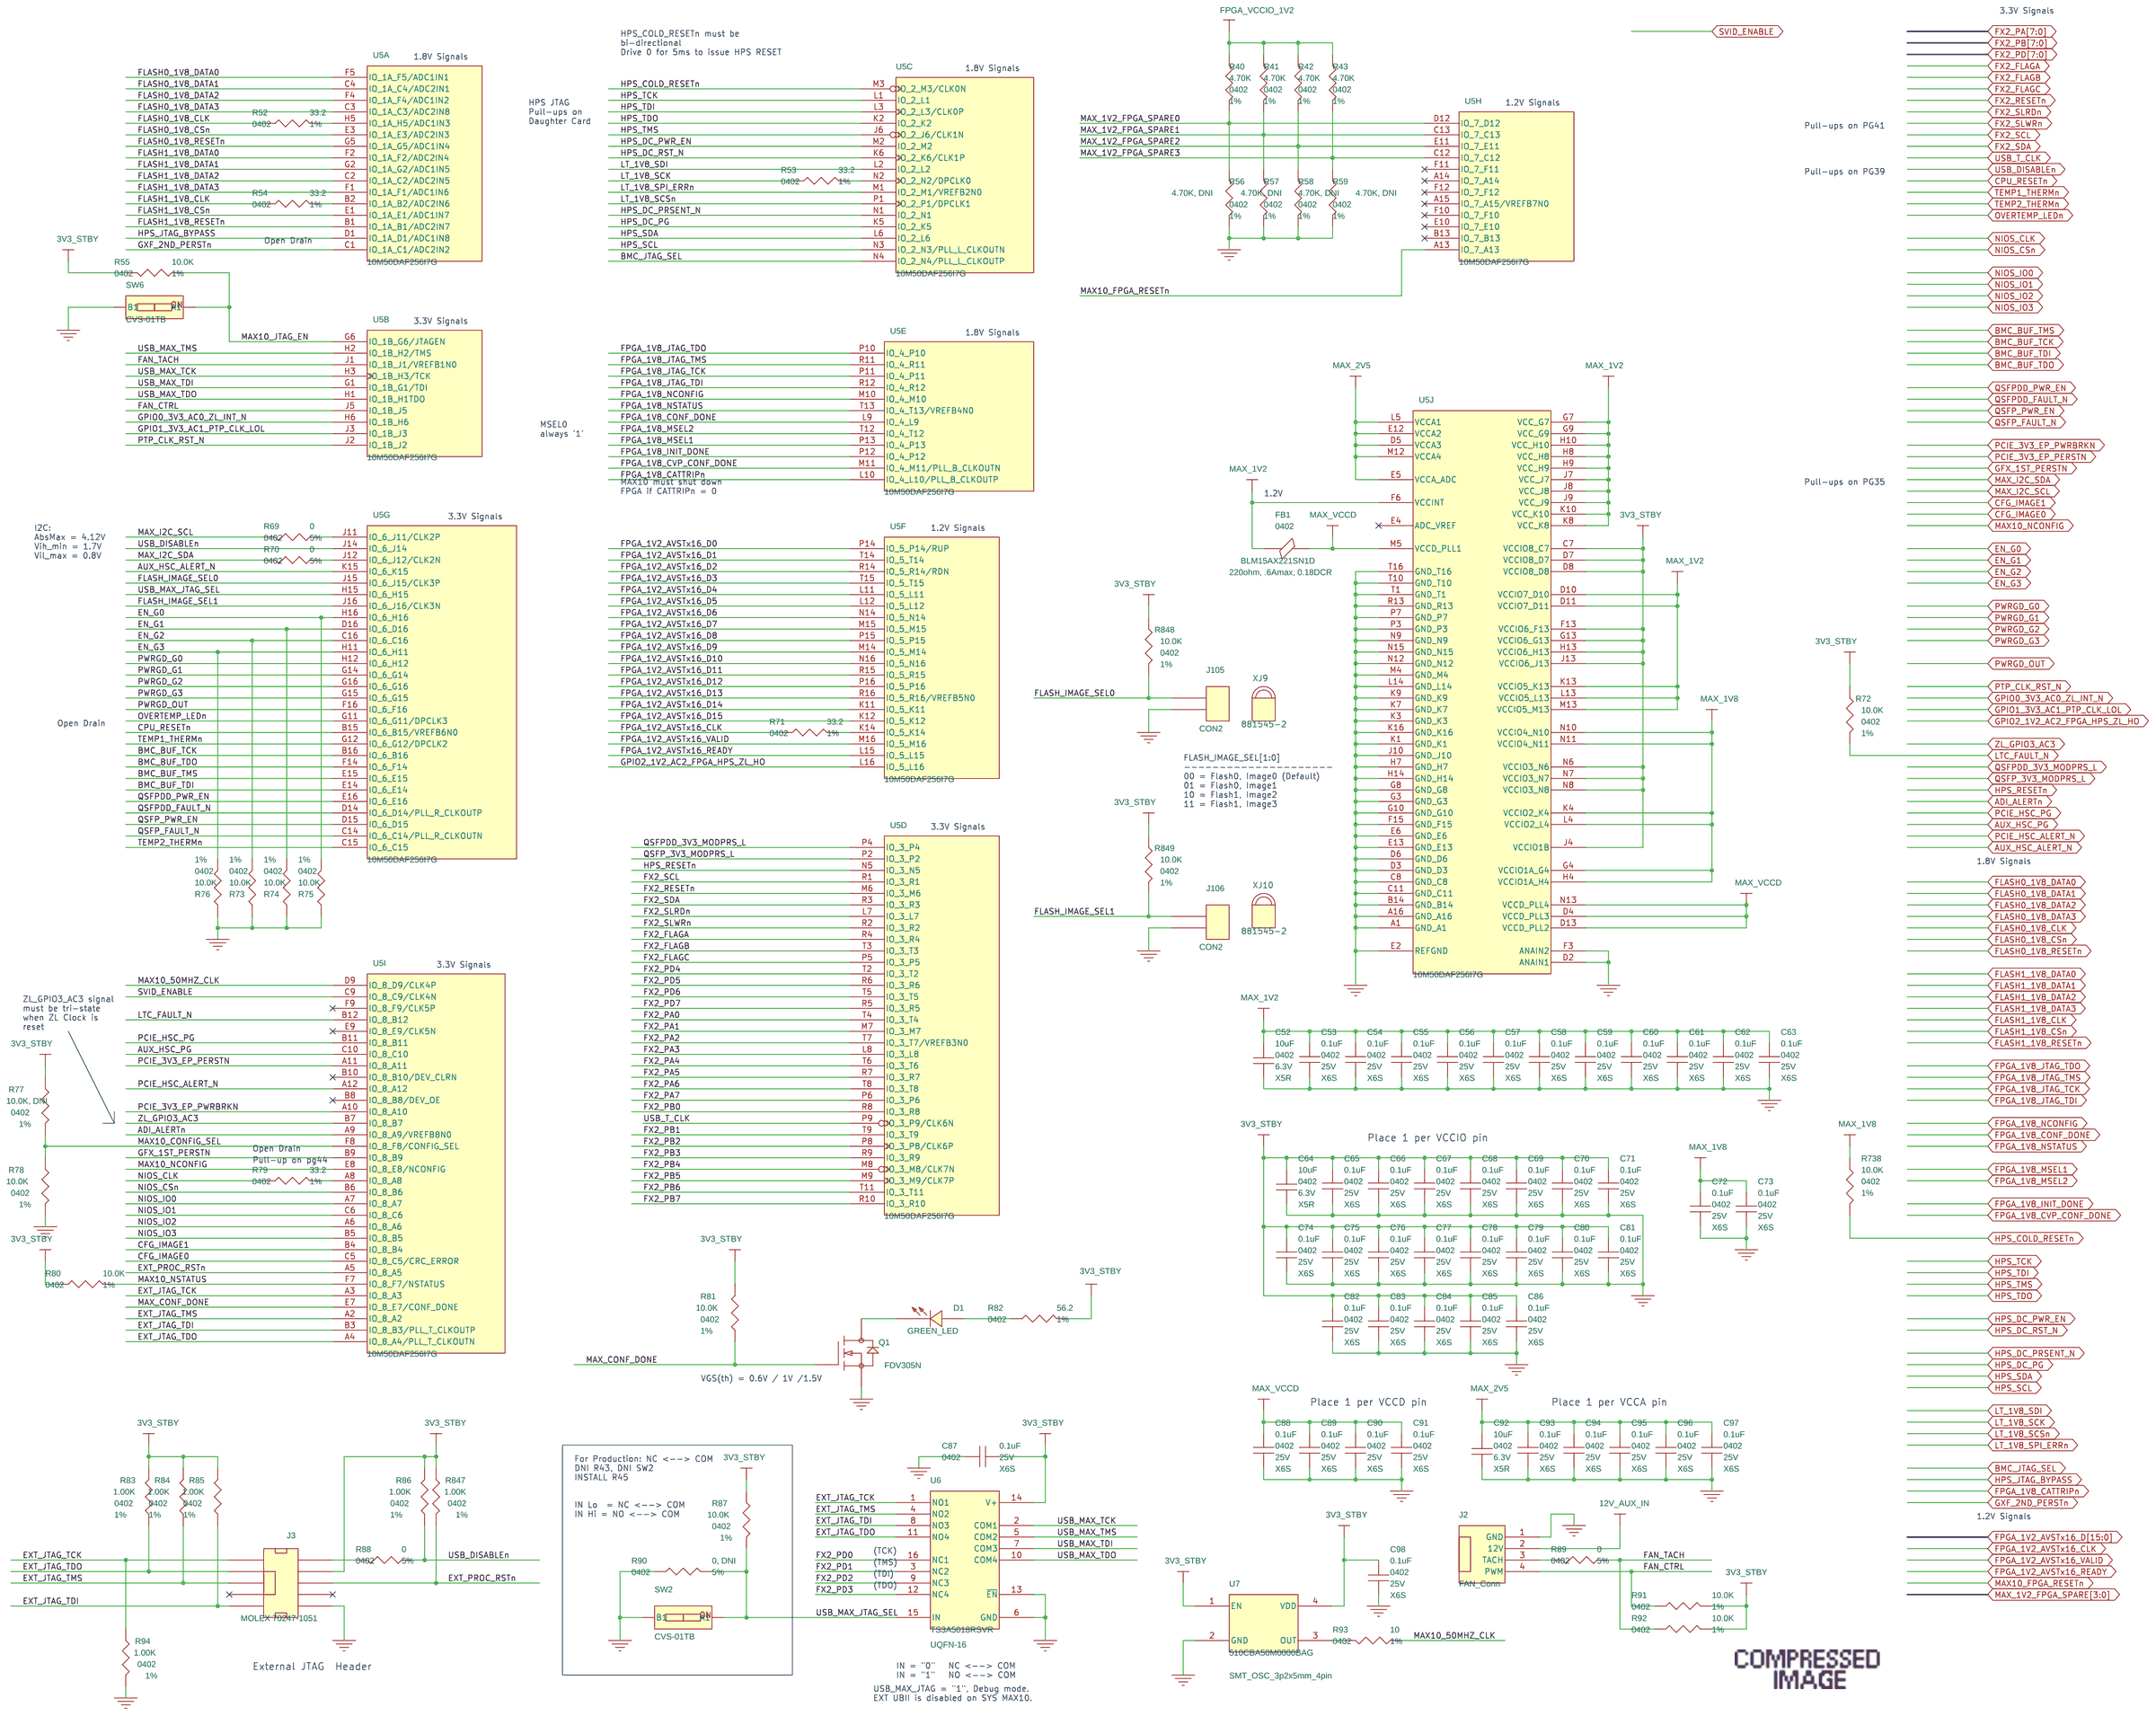
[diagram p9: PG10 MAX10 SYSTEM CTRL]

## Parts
sheet PG08 PCIE EDGE FINGER
C1  0.22uF  [SMC0201IA]
C2  0.22uF  [SMC0201IA]
C6  0.22uF  [SMC0201IA]
C7  0.22uF  [SMC0201IA]
C8  0.22uF  [SMC0201IA]
C9  0.22uF  [SMC0201IA]
C10  0.22uF  [SMC0201IA]
C11  0.22uF  [SMC0201IA]
C12  0.22uF  [SMC0201IA]
C13  0.22uF  [SMC0201IA]
C14  0.22uF  [SMC0201IA]
C15  0.22uF  [SMC0201IA]
C16  1pF  [0402]
C17  1pF  [0402]
C18  0.22uF  [SMC0201IA]
C19  1pF  [0402]
C20  0.22uF  [SMC0201IA]
C21  1pF  [0402]
C22  1pF  [0402]
C23  1pF  [0402]
C24  0.22uF  [SMC0201IA]
C25  1pF  [0402]
C26  0.22uF  [SMC0201IA]
C27  1pF  [0402]
C28  1pF  [0402]
C29  1pF  [0402]
C30  1pF  [0402]
C31  0.22uF  [SMC0201IA]
C32  0.22uF  [SMC0201IA]
C33  0.22uF  [SMC0201IA]
C34  0.22uF  [SMC0201IA]
C35  0.22uF  [SMC0201IA]
C36  0.22uF  [SMC0201IA]
C37  0.1uF  [0402]
C38  0.22uF  [SMC0201IA]
C39  0.22uF  [SMC0201IA]
C40  0.22uF  [SMC0201IA]
C41  0.22uF  [SMC0201IA]
C42  0.22uF  [SMC0201IA]
C43  0.22uF  [SMC0201IA]
C44  0.22uF  [SMC0201IA]
C45  0.22uF  [SMC0201IA]
C46  0.22uF  [SMC0201IA]
C47  0.22uF  [SMC0201IA]
J1  PCIE_Slot  [PCIX-16PORT]
R1  4.70K, DNI  [0402]
R2  4.70K, DNI  [0402]
R3  100K  [0402]
R4  100K  [0402]
R5  10.0K  [0402]
R6  10.0K  [0402]
R7  10.0K, DNI  [0402]
R8  10.0K  [0402]
R12  100K  [0402]
R13  49.9  [0402]
R14  49.9  [0402]
R15  49.9  [0402]
R16  49.9  [0402]
R17  49.9  [0402]
R18  49.9  [0402]
R19  49.9  [0402]
R20  49.9  [0402]
R21  49.9  [0402]
R22  49.9  [0402]
R23  49.9  [0402]
R24  10.0K, DNI  [0402]
R25  10.0K, DNI  [0402]
R26  10.0K, DNI  [0402]
R27  10.0K, DNI  [0402]
R28  10.0K  [0402]
R29  10.0K  [0402]
R30  10.0K  [0402]
R31  10.0K  [0402]
R774  0  [0402]
R6944  0  [0402]
R6945  0  [0402]
SW1  TDA04H0SB1  [DIPSWITCH_SMT_QUAD]
U2  24AA024-I/SN  [SOIC-8]
sheet PG09 FPGA CONFIG FLASH
C48  0.1uF  [0402]
C49  0.1uF  [0402]
C50  1uF  [0402]
C51  1uF  [0402]
R32  10.0K  [0402]
R33  10.0K  [0402]
R34  10.0K  [0402]
R35  10.0K  [0402]
R36  10.0K  [0402]
R37  10.0K  [0402]
R38  10.0K  [0402]
R39  10.0K  [0402]
R770  10.0K  [0402]
R771  10.0K  [0402]
U3  MT25QU02GCBB8E12-0SIT  [T-PBGA24]
U4  MT25QU02GCBB8E12-0SIT  [T-PBGA24]
sheet PG10 MAX10 SYSTEM CTRL
C52  10uF  [0402]
C53  0.1uF  [0402]
C54  0.1uF  [0402]
C55  0.1uF  [0402]
C56  0.1uF  [0402]
C57  0.1uF  [0402]
C58  0.1uF  [0402]
C59  0.1uF  [0402]
C60  0.1uF  [0402]
C61  0.1uF  [0402]
C62  0.1uF  [0402]
C63  0.1uF  [0402]
C64  10uF  [0402]
C65  0.1uF  [0402]
C66  0.1uF  [0402]
C67  0.1uF  [0402]
C68  0.1uF  [0402]
C69  0.1uF  [0402]
C70  0.1uF  [0402]
C71  0.1uF  [0402]
C72  0.1uF  [0402]
C73  0.1uF  [0402]
C74  0.1uF  [0402]
C75  0.1uF  [0402]
C76  0.1uF  [0402]
C77  0.1uF  [0402]
C78  0.1uF  [0402]
C79  0.1uF  [0402]
C80  0.1uF  [0402]
C81  0.1uF  [0402]
C82  0.1uF  [0402]
C83  0.1uF  [0402]
C84  0.1uF  [0402]
C85  0.1uF  [0402]
C86  0.1uF  [0402]
C87  0.1uF  [0402]
C88  0.1uF  [0402]
C89  0.1uF  [0402]
C90  0.1uF  [0402]
C91  0.1uF  [0402]
C92  10uF  [0402]
C93  0.1uF  [0402]
C94  0.1uF  [0402]
C95  0.1uF  [0402]
C96  0.1uF  [0402]
C97  0.1uF  [0402]
C98  0.1uF  [0402]
D1  GREEN_LED  [LED_0603]
FB1  220ohm, .6Amax, 0.18DCR  [0402]
J2  FAN_Conn  [Molex_0470533000]
J3  MOLEX 70247-1051  [Molex_70247-1051]
J105  CON2  [HDR2x1_100MIL]
J106  CON2  [HDR2x1_100MIL]
Q1  FDV305N  [SOT23]
R40  4.70K  [0402]
R41  4.70K  [0402]
R42  4.70K  [0402]
R43  4.70K  [0402]
R52  33.2  [0402]
R53  33.2  [0402]
R54  33.2  [0402]
R55  10.0K  [0402]
R56  4.70K, DNI  [0402]
R57  4.70K, DNI  [0402]
R58  4.70K, DNI  [0402]
R59  4.70K, DNI  [0402]
R69  0  [0402]
R70  0  [0402]
R71  33.2  [0402]
R72  10.0K  [0402]
R73  10.0K  [0402]
R74  10.0K  [0402]
R75  10.0K  [0402]
R76  10.0K  [0402]
R77  10.0K, DNI  [0402]
R78  10.0K  [0402]
R79  33.2  [0402]
R80  10.0K  [0402]
R81  10.0K  [0402]
R82  56.2  [0402]
R83  1.00K  [0402]
R84  1.00K  [0402]
R85  1.00K  [0402]
R86  1.00K  [0402]
R87  10.0K  [0402]
R88  0  [0402]
R89  0  [0402]
R90  0, DNI  [0402]
R91  10.0K  [0402]
R92  10.0K  [0402]
R93  10  [0402]
R94  1.00K  [0402]
R738  10.0K  [0402]
R847  1.00K  [0402]
R848  10.0K  [0402]
R849  10.0K  [0402]
SW2  CVS-01TB  [DIPSWITCH_SMT_SINGLE]
SW6  CVS-01TB  [DIPSWITCH_SMT_SINGLE]
U5  10M50DAF256I7G  [MAX10_FBGA-256]  (sections A,B,C,D,E,F,G,H,I,J)
U6  TS3A5018RSVR  [UQFN-16]
U7  510CBA50M0000BAG  [SMT_OSC_3p2x5mm_4pin]
XJ9  881545-2  [NULL]
XJ10  881545-2  [NULL]

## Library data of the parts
C1 C2 C6-C15 C18 C20 C24 C26 C31-C36 C38-C47 = CAP: CAP - CER, 0.22UF, 6.3V, 10%, X6S, 0201; Item Num: J19343-004; Manufacturer: Murata; Manufacturer Part Num: GRM033C80J224KE90D; Num Pins: 2; PART_SUBCLASS: CAPACITORS; Package: 0201; RATED_VOLTAGE: 6.3V; TOLERANCE: +/-10%; Temperature Coefficient: X6S
C16 C17 C19 C21-C23 C25 C27-C30 = CAP: CAP - CERAMIC, 1PF, +/-0.25PF,  50V, 0402, C0G; AGILE_LINK: http://sj-agile9app/Agile/PLMServlet?action=OpenEmailObject&classid=10000&objid=218192110; Item Num: K13552-001; LIFECYCLE_PHASE: Active; MFR_LIFECYCLE: Active; Manufacturer: Murata; Manufacturer Part Num: GJM1555C1H1R0CB01D; Num Pins: 2; PART_SUBCLASS: CAPACITORS; RATED_VOLTAGE: 50V; RoHS Compliant: RoHS Compliant; Temperature Coefficient: C0G
C37 C48 C49 C53-C63 C65-C91 C93-C98 = CAP: CAP CER 0.1UF 25V X6S 0402; Dielectric: X6S; IPN: K19434-001; Item Num: K19434-001; LIFECYCLE_PHASE: Active; Lead Free Status: Lead Free; MFR_LIFECYCLE: Active; Manufacturer: Murata; Manufacturer Part Num: GRM155C81E104KA12D; Num Pins: 2; PART_SUBCLASS: CAPACITORS; Part Class: CAPACITORS; RATED_VOLTAGE: 25V; RoHS Compliant: RoHS Compliant; Temperature Coefficient: X6S; Tolerance: 10%
J1 = PCIE_Bracket_X16_1: Item Num: NA; Manufacturer: NA; Manufacturer's Part No.: NA
R1 R2 R40-R43 R56-R59 = RESISTOR: RES,4.70K OHMS,1.0%,1/16W,0402; AGILE_LINK: http://sj-agile9app/Agile/PLMServlet?action=OpenEmailObject&classid=10000&objid=146753272; Item Num: A93548-517; LIFECYCLE_PHASE: Active; Lead Free Status: Yes; MFR_LIFECYCLE: Active; Manufacturer: Vishay; Manufacturer Part Num: CRCW04024K70FKED; Num Pins: 2; PART_SUBCLASS: RESISTORS; POWER: 1/16W; RESISTANCE: 4.7K; RoHS Compliant: Yes; TOLERANCE: 1%
R3 R4 R12 = RESISTOR: RES,100K OHMS,1.0%,1/16W,0402; Item Num: A78422-001; Lead Free Status: Yes; Manufacturer: Panasonic; Manufacturer Part Num: ERJ-2RKF1003X; Num Pins: 2; Part Class: Resistors; RoHS Compliant: Yes; TOLERANCE: 1%
R5 R6 R8 R28-R39 R55 R72-R76 R78 R80 R81 R87 R91 R92 R738 R770 R771 R848 R849 = RESISTOR: RES,10.0K OHMS,1.0%,1/16W, 0402; AGILE_LINK: http://sj-agile9app/Agile/PLMServlet?action=OpenEmailObject&classid=10000&objid=146548997; Item Num: K28115-001; LIFECYCLE_PHASE: Active; Lead Free Status: Yes; MFR_LIFECYCLE: Active; Manufacturer: Panasonic; Manufacturer Part Num: ERJ-2RKF1002X; Num Pins: 2; PART_SUBCLASS: RESISTORS; POWER: 1/16W; RoHS Compliant: Yes; TOLERANCE: 1%
R7 R24-R27 R77 = RESISTOR: RES,10.0K OHMS,1.0%,1/16W, 0402; AGILE_LINK: http://sj-agile9app/Agile/PLMServlet?action=OpenEmailObject&classid=10000&objid=146548997; Item Num: K28115-001; LIFECYCLE_PHASE: Active; Lead Free Status: Yes; MFR_LIFECYCLE: Active; Manufacturer: Panasonic; Manufacturer Part Num: ERJ-2RKF1002X; Num Pins: 2; PART_SUBCLASS: RESISTORS; POWER: 1/16W; RESISTANCE: 10.0K; RoHS Compliant: Yes; TOLERANCE: 1%
R13-R23 = RESISTOR: RES SMD 49.9 OHM 1% 1/10W 0402; AGILE_LINK: http://sj-agile9app/Agile/PLMServlet?action=OpenEmailObject&classid=10000&objid=146548997; Item Num: K16545-001; LIFECYCLE_PHASE: Active; Lead Free Status: Yes; MFR_LIFECYCLE: Active; Manufacturer: NIC Components Corp.; Manufacturer Part Num: NRC04F49R9TRF; Num Pins: 2; PART_SUBCLASS: RESISTORS; POWER: 1/16W; Part Class: Resistors; RoHS Compliant: Yes; TOLERANCE: 1%
R69 R70 R88 R89 R774 R6944 R6945 = RESISTOR: RES ZERO OHM 1/16W 5% 0402 SMD; Item Num: A93549-001; Lead Free Status: No; Manufacturer: Yageo; Manufacturer Part Num: RC0402JR-070RL; Num Pins: 2; Part Class: RESISTORS; RoHS Compliant: Yes; Tolerance: 5%
SW1 = SPST4: SWITCHES - 4 POS, 8 PIN, Ultra-mini SMT Half-pitch Slider DIP Switch; Item Num: K15518-001; Lead Free Status: Yes; Manufacturer: C & K Components/ITT Industries; Num Pins: 8; Part Class: Switches; Price: 0; RoHS Compliant: Yes; Supplier: 8
U2 = 24AA024: IC,EEPROM,BL,SOIC,400KHz,N/A,I2C,2KB,N/A; Item Num: K41506-001; Manufacturer: Microchip
C50 C51 = CAP: CAP CER 1UF 25V X6S 0402; Item Num: H81594-001; Lead Free Status: Yes; Manufacturer: Murata; Manufacturer Part Num: GRM155C81E105KE11D; Num Pins: 2; Part Class: CAPACITORS; RATED_VOLTAGE: 25V; RoHS Compliant: Yes; Temperature Coefficient: X6S
U3 U4 = MT25QU01GBBB: IC, 2Gb 1.8V Serial NOR Flash Memory; Item Num: K59819-001; Manufacturer: Micron
C52 C64 C92 = CAP: CAP CER 10UF 6.3V X5R 0402; AGILE_LINK: http://sj-agile9app/Agile/PLMServlet?action=OpenEmailObject&classid=10000&objid=257560276; Item Num: K46607-001; LIFECYCLE_PHASE: Active; Lead Free Status: Lead Free; MFR_LIFECYCLE: Active; Manufacturer: Murata Electronics North America; Manufacturer Part Num: GRJ155R60J106ME11D; Num Pins: 2; PART_SUBCLASS: CAPACITORS; Part Class: CAPACITORS; RATED_VOLTAGE: 6.3V; RoHS Compliant: RoHS Compliant; TOLERANCE: 20%; Temperature Coefficient: X5R
D1 = LED_WURTH: LED - BRIGHT GREEN, VF=2V, IF=0.03A, 0603; Item Num: K15375-001; LIFECYCLE_PHASE: Active; Lead Free Status: Lead Free; Manufacturer: Wurth Electroniks; Manufacturer Part Num: 150060VS75000; Num Pins: 2; PART_SUBCLASS: LEDS; Part Class: LEDS; RoHS Compliant: RoHS Compliant
FB1 = BEAD_FERRITE_SM: FERRITE BEAD 220 OHM 0402 1LN; Item Num: A51464-023; LIFECYCLE_PHASE: Active; MFR_LIFECYCLE: Active; Manufacturer: Murata; Manufacturer Part Num: BLM15AX221SN1D; Num Pins: 2; Part Class: Inductors; RoHS Compliant: Yes
J2 = FAN_Conn_0: 4 POSITIONS HEADER, UNSHROUDED CONNECTOR 0.100" (2.54MM) THROUGH HOLE TIN; Item Num: K21517-001; Manufacturer: Molex; Manufacturer Name: Molex; Manufacturer Part Num: 0470533000
J3 = 70247-1051: CONN - HDR2X5 100 MIL SHROUDED RIGHT-ANGLE; Device: J23; Item Num: K10905-001; Lead Free Status: No; Manufacturer: Molex; Num Pins: 10; Part Class: Connectors; Price: 1; RoHS Compliant: Yes
J105 J106 = CON2: 2X1 .100" CENTER HEADER; ID: 213872; Item Num: K10869-001; Lead Free Status: No; Manufacturer: 3M/ESD; Manufacturer Part Num: 929665-09-36-I; Manufacturer's Part No.: 929665-09-36-I; Num Pins: 2; Part Class: Connectors; Price: 0
Q1 = PWRMOSFET_EN_GSD_0: IC, MOSFET, N-Channel, 20V; Item Num: K21465-001; Manufacturer: Fairchild
R52-R54 R71 R79 = RESISTOR: RES,33.2 OHMS,1.0%,1/16W,0402; AGILE_LINK: http://sj-agile9app/Agile/PLMServlet?action=OpenEmailObject&classid=10000&objid=146932246; Item Num: J38619-001; LIFECYCLE_PHASE: Active; MFR_LIFECYCLE: Active; Manufacturer: Panasonic; Manufacturer Part Num: ERJ-2RKF33R2X; Num Pins: 2; PART_SUBCLASS: RESISTORS; POWER: 1/16W; RESISTANCE: 10; RoHS Compliant: RoHS Compliant; TOLERANCE: 1%
R82 = RESISTOR_0: RES,56.2 OHMS,1.0%,1/16W,0402; Item Num: K16543-001; Lead Free Status: No; Manufacturer: Panasonic; Manufacturer Part Num: ERJ-2RKF56R2X; Num Pins: 2; Part Class: RESISTORS; Price: 0; RoHS Compliant: Yes; Tolerance: 1%
R83-R86 R94 R847 = RESISTOR: RES,1.00K OHMS,1.0%,1/16W,0402; Item Num: G60609-021; Lead Free Status: Yes; Manufacturer: Panasonic; Manufacturer Part Num: ERJ-2RKF1001X; Num Pins: 2; Part Class: Resistors; TOLERANCE: 1%
R90 = RESISTOR: RES ZERO OHM 1/16W 5% 0402 SMD; IPN: A93549-001; Item Num: A93549-001; Lead Free Status: Yes; Manufacturer: Yageo; Manufacturer Part Num: RC0402JR-070RL; Num Pins: 2; Part Class: RESISTORS; RoHS Compliant: Yes; Tolerance: 5%
R93 = RESISTOR: RES, 10 OHM, 1%, 1/16W, 0402; Item Num: A80345-001; LIFECYCLE_PHASE: Active; Lead Free Status: Yes; Manufacturer: Panasonic; Manufacturer Part Num: ERJ-2RKF10R0X; Num Pins: 2; PART_SUBCLASS: RESISTORS; POWER: 1/16W; Part Class: Resistors; RoHS Compliant: Yes; TOLERANCE: 1%
SW2 SW6 = SPST4_0: SWITCH SLIDE DIP SPST 100MA 6V; AGILE_LINK: http://sj-agile9app/Agile/PLMServlet?action=OpenEmailObject&classid=10000&objid=258073635; Item Num: K75336-001; LIFECYCLE_PHASE: Preliminary; Lead Free Status: Yes; MFR_LIFECYCLE: Active; Manufacturer: Nidec Copal Electronics; Num Pins: 8; PART_SUBCLASS: SWITCHES; RoHS Compliant: RoHS Compliant
U5 = 1M50DAF256I7G: IC, MAX10, 10M50, BGA-256; Item Num: 967772; Manufacturer: Intel
U6 = TS3A5018RSVR_0: IC,LIN,ANALOGSWITCH,UQFN,TS3A5018,; Item Num: H28953-001; Manufacturer: Texas Instrument
U7 = SiLabs_510GBA25M0000BAGR: IC, Crystal Oscillator 50.0000MHz; Item Num: K22144-001; Manufacturer: SiLabs
XJ9 XJ10 = SHUNT: SHUNT, 2 Position, 0.100"; ID: 213681; Item Num: H23022-002; Lead Free Status: No; Manufacturer: AMP/Tyco; Num Pins: 2; Part Class: Connectors; RoHS Compliant: Yes

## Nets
3V3_STBY: C64.2 C65.1 C66.1 C67.1 C68.1 C69.1 C70.1 C71.1 C74.1 C75.1 C76.1 C77.1 C78.1 C79.1 C80.1 C81.1 C82.1 C83.1 C84.1 C85.1 C86.1 C87.1 C98.2 J3.4 R5.2 R6.1 R12.1 R55.2 R72.1 R77.1 R80.2 R81.2 R82.2 R83.1 R84.1 R85.1 R86.1 R87.1 R91.2 R92.2 R847.1 R848.1 R849.1 U5.C7(VCCIO8) U5.D7(VCCIO8) U5.D8(VCCIO8) U5.F13(VCCIO6) U5.G13(VCCIO6) U5.H13(VCCIO6) U5.J4(VCCIO1B) U5.J13(VCCIO6) U5.N6(VCCIO3) U5.N7(VCCIO3) U5.N8(VCCIO3) U6.14(V+) U7.1(EN) U7.4(VDD) ; also on sheet 16 22 28 32 34 36 37 38 40 41 48 49 50 51 52 53 54 58
12V_AUX_IN: J2.2(12V) ; also on sheet 40 42 43 44 45 46 58
GND: C37.1 C48.1 C49.1 C50.1 C51.1 C52.1 C53.2 C54.2 C55.2 C56.2 C57.2 C58.2 C59.2 C60.2 C61.2 C62.2 C63.2 C64.1 C65.2 C66.2 C67.2 C68.2 C69.2 C70.2 C71.2 C72.2 C73.2 C74.2 C75.2 C76.2 C77.2 C78.2 C79.2 C80.2 C81.2 C82.2 C83.2 C84.2 C85.2 C86.2 C87.2 C88.2 C89.2 C90.2 C91.2 C92.1 C93.2 C94.2 C95.2 C96.2 C97.2 C98.1 J1.A4(GND) J1.A12(GND) J1.A15(GND) J1.A18(GND) J1.A20(GND) J1.A23(GND) J1.A24(GND) J1.A27(GND) J1.A28(GND) J1.A31(GND) J1.A34(GND) J1.A37(GND) J1.A38(GND) J1.A41(GND) J1.A42(GND) J1.A45(GND) J1.A46(GND) J1.A49(GND) J1.A51(GND) J1.A54(GND) J1.A55(GND) J1.A58(GND) J1.A59(GND) J1.A62(GND) J1.A63(GND) J1.A66(GND) J1.A67(GND) J1.A70(GND) J1.A71(GND) J1.A74(GND) J1.A75(GND) J1.A78(GND) J1.A79(GND) J1.A82(GND) J1.B4(GND) J1.B7(GND) J1.B13(GND) J1.B16(GND) J1.B18(GND) J1.B21(GND) J1.B22(GND) J1.B25(GND) J1.B26(GND) J1.B29(GND) J1.B32(GND) J1.B35(GND) J1.B36(GND) J1.B39(GND) J1.B40(GND) J1.B43(GND) J1.B44(GND) J1.B47(GND) J1.B49(GND) J1.B52(GND) J1.B53(GND) J1.B56(GND) J1.B57(GND) J1.B60(GND) J1.B61(GND) J1.B64(GND) J1.B65(GND) J1.B68(GND) J1.B69(GND) J1.B72(GND) J1.B73(GND) J1.B76(GND) J1.B77(GND) J1.B80(GND) J2.1(GND) J3.10 J105.2 J106.2 Q1.2(SOURCE) R13.2 R14.2 R15.2 R16.2 R17.2 R18.2 R19.2 R20.2 R21.2 R22.2 R23.2 R28.1 R29.1 R30.1 R31.1 R56.1 R57.1 R58.1 R59.1 R73.1 R74.1 R75.1 R76.1 R78.2 R90.2 R94.2 R770.1 R771.1 SW2.2(B1) SW6.2(B1) U2.4(VSS) U3.B3(VSS) U4.B3(VSS) U5.A1(GND) U5.A16(GND) U5.B14(GND) U5.C8(GND) U5.C11(GND) U5.D2(ANAIN1) U5.D3(GND) U5.D6(GND) U5.E2(REFGND) U5.E6(GND) U5.E13(GND) U5.F3(ANAIN2) U5.F15(GND) U5.G3(GND) U5.G8(GND) U5.G10(GND) U5.H7(GND) U5.H14(GND) U5.J10(GND) U5.K1(GND) U5.K3(GND) U5.K7(GND) U5.K9(GND) U5.K16(GND) U5.L14(GND) U5.M4(GND) U5.N9(GND) U5.N12(GND) U5.N15(GND) U5.P3(GND) U5.P7(GND) U5.R13(GND) U5.T1(GND) U5.T10(GND) U5.T16(GND) U6.6(GND) U6.13(~{EN}) U7.2(GND) ; also on sheet 11 12 13 15 16 19 20 21 22 23 24 25 26 27 28 29 30 31 32 33 34 35 36 37 38 39 40 41 42 43 44 45 46 47 48 49 50 51 52 53 54 55 56 58
ADI_ALERTn: U5.A9(IO_8_A9/VREFB8N0) ; also on sheet 49 50
AUX_HSC_ALERT_N: U5.K15(IO_6) ; also on sheet 40
AUX_HSC_PG: U5.C10(IO_8) ; also on sheet 40
BMC_BUF_TCK: U5.B16(IO_6) ; also on sheet 34
BMC_BUF_TDI: U5.E14(IO_6) ; also on sheet 34
BMC_BUF_TDO: U5.F14(IO_6) ; also on sheet 34
BMC_BUF_TMS: U5.E15(IO_6) ; also on sheet 34
BMC_JTAG_SEL: U5.N4(IO_2_N4/PLL_L_CLKOUTP) ; also on sheet 11
CFG_IMAGE0: U5.C5(IO_8_C5/CRC_ERROR) ; also on sheet 36
CFG_IMAGE1: U5.B4(IO_8) ; also on sheet 36
CPU_RESETn: U5.B15(IO_6_B15/VREFB6N0) ; also on sheet 34 36
EN_G0: R75.2 U5.H16(IO_6) ; also on sheet 41
EN_G1: R74.2 U5.D16(IO_6) ; also on sheet 42 43 44 45 46 47 48 49
EN_G2: R73.2 U5.C16(IO_6) ; also on sheet 50
EN_G3: R76.2 U5.H11(IO_6) ; also on sheet 49 50 53
EXT_JTAG_TCK: J3.1 R94.1 U5.A3(IO_8) U6.1(NO1)
EXT_JTAG_TDI: J3.9 R85.2 U5.B3(IO_8_B3/PLL_T_CLKOUTP) U6.8(NO3)
EXT_JTAG_TDO: J3.3 R83.2 U5.A4(IO_8_A4/PLL_T_CLKOUTN) U6.11(NO4)
EXT_JTAG_TMS: J3.5 R84.2 U5.A2(IO_8) U6.4(NO2)
EXT_PROC_RSTn: J3.6 R847.2 U5.A5(IO_8)
FAN_CTRL: J2.4(PWM) R91.1 U5.J5(IO_1B)
FAN_TACH: R89.2 R92.1 U5.J1(IO_1B_J1/VREFB1N0)
FLASH0_1V8_CLK: R52.2 R770.2 U4.B2(C)
FLASH0_1V8_CSn: R38.1 U4.C2(S#) U5.E3(IO_1A_E3/ADC2IN3)
FLASH0_1V8_DATA0: U4.D3(DQ0) U5.F5(IO_1A_F5/ADC1IN1)
FLASH0_1V8_DATA1: U4.D2(DQ1) U5.C4(IO_1A_C4/ADC2IN1)
FLASH0_1V8_DATA2: R32.1 U4.C4(W#/DQ2) U5.F4(IO_1A_F4/ADC1IN2)
FLASH0_1V8_DATA3: R33.1 U4.D4(DQ3) U5.C3(IO_1A_C3/ADC2IN8)
FLASH0_1V8_RESETn: R39.1 U4.A4(RESET#/DNU) U5.G5(IO_1A_G5/ADC1IN4)
FLASH1_1V8_CLK: R54.2 R771.2 U3.B2(C)
FLASH1_1V8_CSn: R36.1 U3.C2(S#) U5.E1(IO_1A_E1/ADC1IN7)
FLASH1_1V8_DATA0: U3.D3(DQ0) U5.F2(IO_1A_F2/ADC2IN4)
FLASH1_1V8_DATA1: U3.D2(DQ1) U5.G2(IO_1A_G2/ADC1IN5)
FLASH1_1V8_DATA2: R34.1 U3.C4(W#/DQ2) U5.C2(IO_1A_C2/ADC2IN5)
FLASH1_1V8_DATA3: R35.1 U3.D4(DQ3) U5.F1(IO_1A_F1/ADC1IN6)
FLASH1_1V8_RESETn: R37.1 U3.A4(RESET#/DNU) U5.B1(IO_1A_B1/ADC2IN7)
FLASH_IMAGE_SEL0: J105.1 R848.2 U5.J15(IO_6_J15/CLK3P)
FLASH_IMAGE_SEL1: J106.1 R849.2 U5.J16(IO_6_J16/CLK3N)
FPGA_1V2_AVSTx16_CLK: R71.2 ; also on sheet 16
FPGA_1V2_AVSTx16_D0: U5.P14(IO_5_P14/RUP) ; also on sheet 16
FPGA_1V2_AVSTx16_D1: U5.T14(IO_5) ; also on sheet 16
FPGA_1V2_AVSTx16_D2: U5.R14(IO_5_R14/RDN) ; also on sheet 16
FPGA_1V2_AVSTx16_D3: U5.T15(IO_5) ; also on sheet 16
FPGA_1V2_AVSTx16_D4: U5.L11(IO_5) ; also on sheet 16
FPGA_1V2_AVSTx16_D5: U5.L12(IO_5) ; also on sheet 16
FPGA_1V2_AVSTx16_D6: U5.N14(IO_5) ; also on sheet 16
FPGA_1V2_AVSTx16_D7: U5.M15(IO_5) ; also on sheet 16
FPGA_1V2_AVSTx16_D8: U5.P15(IO_5) ; also on sheet 16
FPGA_1V2_AVSTx16_D9: U5.M14(IO_5) ; also on sheet 16
FPGA_1V2_AVSTx16_D10: U5.N16(IO_5) ; also on sheet 16
FPGA_1V2_AVSTx16_D11: U5.R15(IO_5) ; also on sheet 16
FPGA_1V2_AVSTx16_D12: U5.P16(IO_5) ; also on sheet 16
FPGA_1V2_AVSTx16_D13: U5.R16(IO_5_R16/VREFB5N0) ; also on sheet 16
FPGA_1V2_AVSTx16_D14: U5.K11(IO_5) ; also on sheet 16
FPGA_1V2_AVSTx16_D15: U5.K12(IO_5) ; also on sheet 16
FPGA_1V2_AVSTx16_READY: U5.L15(IO_5) ; also on sheet 16
FPGA_1V2_AVSTx16_VALID: U5.M16(IO_5) ; also on sheet 16
FPGA_1V8_CATTRIPn: U5.L10(IO_4_L10/PLL_B_CLKOUTP) ; also on sheet 11
FPGA_1V8_CONF_DONE: U5.L9(IO_4) ; also on sheet 11 36
FPGA_1V8_CVP_CONF_DONE: U5.M11(IO_4_M11/PLL_B_CLKOUTN) ; also on sheet 11
FPGA_1V8_INIT_DONE: U5.P12(IO_4) ; also on sheet 11
FPGA_1V8_JTAG_TCK: U5.P11(IO_4) ; also on sheet 11
FPGA_1V8_JTAG_TDI: U5.R12(IO_4) ; also on sheet 11
FPGA_1V8_JTAG_TDO: U5.P10(IO_4) ; also on sheet 11
FPGA_1V8_JTAG_TMS: U5.R11(IO_4) ; also on sheet 11
FPGA_1V8_MSEL1: U5.P13(IO_4) ; also on sheet 11
FPGA_1V8_MSEL2: U5.T12(IO_4) ; also on sheet 11
FPGA_1V8_NCONFIG: U5.M10(IO_4) ; also on sheet 11
FPGA_1V8_NSTATUS: U5.T13(IO_4_T13/VREFB4N0) ; also on sheet 11
FPGA_VCCIO_1V2: R40.2 R41.2 R42.2 R43.2 ; also on sheet 16 23 25 26 27 31 34 35 36 39 50 54 55 56
FX2_FLAGA: U5.R4(IO_3) ; also on sheet 38
FX2_FLAGB: U5.T3(IO_3) ; also on sheet 38
FX2_FLAGC: U5.P5(IO_3) ; also on sheet 38
FX2_PA0: U5.T4(IO_3) ; also on sheet 38
FX2_PA1: U5.M7(IO_3) ; also on sheet 38
FX2_PA2: U5.T7(IO_3_T7/VREFB3N0) ; also on sheet 38
FX2_PA3: U5.L8(IO_3) ; also on sheet 38
FX2_PA4: U5.T6(IO_3) ; also on sheet 38
FX2_PA5: U5.R7(IO_3) ; also on sheet 38
FX2_PA6: U5.T8(IO_3) ; also on sheet 38
FX2_PA7: U5.P6(IO_3) ; also on sheet 38
FX2_PB0: U5.R8(IO_3) ; also on sheet 38
FX2_PB1: U5.T9(IO_3) ; also on sheet 38
FX2_PB2: U5.P8(IO_3_P8/CLK6P) ; also on sheet 38
FX2_PB3: U5.R9(IO_3) ; also on sheet 38
FX2_PB4: U5.M8(IO_3_M8/CLK7N) ; also on sheet 38
FX2_PB5: U5.M9(IO_3_M9/CLK7P) ; also on sheet 38
FX2_PB6: U5.T11(IO_3) ; also on sheet 38
FX2_PB7: U5.R10(IO_3) ; also on sheet 38
FX2_PD0: U6.16(NC1) ; also on sheet 38
FX2_PD1: U6.3(NC2) ; also on sheet 38
FX2_PD2: U6.9(NC3) ; also on sheet 38
FX2_PD3: U6.12(NC4) ; also on sheet 38
FX2_PD4: U5.T2(IO_3) ; also on sheet 38
FX2_PD5: U5.R6(IO_3) ; also on sheet 38
FX2_PD6: U5.T5(IO_3) ; also on sheet 38
FX2_PD7: U5.R5(IO_3) ; also on sheet 38
FX2_RESETn: U5.M6(IO_3) ; also on sheet 38
FX2_SCL: U5.R1(IO_3) ; also on sheet 38
FX2_SDA: U5.R3(IO_3) ; also on sheet 38
FX2_SLRDn: U5.L7(IO_3) ; also on sheet 38
FX2_SLWRn: U5.R2(IO_3) ; also on sheet 38
GFX_1ST_PERSTN: U5.B9(IO_8) ; also on sheet 22
GPIO0_3V3_AC0_ZL_INT_N: U5.H6(IO_1B) ; also on sheet 32
GPIO1_3V3_AC1_PTP_CLK_LOL: U5.J3(IO_1B) ; also on sheet 32
GPIO2_1V2_AC2_FPGA_HPS_ZL_HO: U5.L16(IO_5) ; also on sheet 34
GXF_2ND_PERSTn: U5.C1(IO_1A_C1/ADC2IN2) ; also on sheet 22 34 36
HPS_COLD_RESETn: R738.1 U5.M3(IO_2_M3/CLK0N) ; also on sheet 11
HPS_DC_PG: U5.K5(IO_2) ; also on sheet 28
HPS_DC_PRSENT_N: U5.N1(IO_2) ; also on sheet 28
HPS_DC_PWR_EN: U5.M2(IO_2) ; also on sheet 28
HPS_DC_RST_N: U5.K6(IO_2_K6/CLK1P) ; also on sheet 28
HPS_JTAG_BYPASS: U5.D1(IO_1A_D1/ADC1IN8) ; also on sheet 11
HPS_RESETn: U5.N5(IO_3) ; also on sheet 36
HPS_SCL: U5.N3(IO_2_N3/PLL_L_CLKOUTN) ; also on sheet 28
HPS_SDA: U5.L6(IO_2) ; also on sheet 28
HPS_TCK: U5.L1(IO_2) ; also on sheet 28
HPS_TDI: U5.L3(IO_2_L3/CLK0P) ; also on sheet 28
HPS_TDO: U5.K2(IO_2) ; also on sheet 28
HPS_TMS: U5.J6(IO_2_J6/CLK1N) ; also on sheet 28
LT_1V8_SCK: R53.2 ; also on sheet 34
LT_1V8_SCSn: U5.P1(IO_2_P1/DPCLK1) ; also on sheet 34
LT_1V8_SDI: U5.L2(IO_2) ; also on sheet 34
LT_1V8_SPI_ERRn: U5.M1(IO_2_M1/VREFB2N0) ; also on sheet 34
LTC_FAULT_N: R72.2 U5.B12(IO_8) ; also on sheet 42
MAX10_50MHZ_CLK: R93.2 U5.D9(IO_8_D9/CLK4P)
MAX10_CONFIG_SEL: R77.2 R78.1 U5.F8(IO_8_F8/CONFIG_SEL)
MAX10_FPGA_RESETn: U5.A13(IO_7) ; also on sheet 16
MAX10_JTAG_EN: R55.1 SW6.1(A1) U5.G6(IO_1B_G6/JTAGEN)
MAX10_NCONFIG: U5.E8(IO_8_E8/NCONFIG) ; also on sheet 58
MAX10_NSTATUS: R80.1 U5.F7(IO_8_F7/NSTATUS)
MAX_1V2: C52.2 C53.1 C54.1 C55.1 C56.1 C57.1 C58.1 C59.1 C60.1 C61.1 C62.1 C63.1 FB1.2 U5.D10(VCCIO7) U5.D11(VCCIO7) U5.F6(VCCINT) U5.G7(VCC) U5.G9(VCC) U5.H8(VCC) U5.H9(VCC) U5.H10(VCC) U5.J7(VCC) U5.J8(VCC) U5.J9(VCC) U5.K8(VCC) U5.K10(VCC) U5.K13(VCCIO5) U5.L13(VCCIO5) U5.M13(VCCIO5) ; also on sheet 58
MAX_1V2_FPGA_SPARE0: R40.1 R56.2 U5.D12(IO_7) ; also on sheet 16
MAX_1V2_FPGA_SPARE1: R41.1 R57.2 U5.C13(IO_7) ; also on sheet 16
MAX_1V2_FPGA_SPARE2: R42.1 R58.2 U5.E11(IO_7) ; also on sheet 16
MAX_1V2_FPGA_SPARE3: R43.1 R59.2 U5.C12(IO_7) ; also on sheet 16
MAX_1V8: C48.2 C49.2 C50.2 C51.2 C72.1 C73.1 R32.2 R33.2 R34.2 R35.2 R36.2 R37.2 R38.2 R39.2 R738.2 U3.B4(VCC) U4.B4(VCC) U5.G4(VCCIO1A) U5.H4(VCCIO1A) U5.K4(VCCIO2) U5.L4(VCCIO2) U5.N10(VCCIO4) U5.N11(VCCIO4) ; also on sheet 11 34 58
MAX_2V5: C92.2 C93.1 C94.1 C95.1 C96.1 C97.1 U5.D5(VCCA3) U5.E5(VCCA_ADC) U5.E12(VCCA2) U5.L5(VCCA1) U5.M12(VCCA4) ; also on sheet 58
MAX_CONF_DONE: Q1.1(GATE) R81.1 U5.E7(IO_8_E7/CONF_DONE)
MAX_I2C_SCL: R69.1 R6944.2 ; also on sheet 32 33 34 37 40 42 49 50
MAX_I2C_SDA: R70.1 R6945.2 ; also on sheet 32 33 34 37 40 42 49 50
MAX_VCCD: C88.1 C89.1 C90.1 C91.1 FB1.1 U5.D4(VCCD_PLL3) U5.D13(VCCD_PLL2) U5.M5(VCCD_PLL1) U5.N13(VCCD_PLL4)
NIOS_CLK: R79.2 ; also on sheet 37
NIOS_CSn: U5.B6(IO_8) ; also on sheet 37
NIOS_IO0: U5.A7(IO_8) ; also on sheet 37
NIOS_IO1: U5.C6(IO_8) ; also on sheet 37
NIOS_IO2: U5.A6(IO_8) ; also on sheet 37
NIOS_IO3: U5.B5(IO_8) ; also on sheet 37
OVERTEMP_LEDn: U5.G11(IO_6_G11/DPCLK3) ; also on sheet 36
PCIE_3V3_AUX: C37.2 J1.B10(+3_3VAUX) R3.1 R4.1 R8.2 R24.2 R25.2 R26.2 R27.2 U2.8(VCC)
PCIE_3V3_EP_CLKREQn: C16.1 J1.B12(RSVD1)
PCIE_3V3_EP_PERSTN: J1.A11(PERST_N) R6.2 U5.A11(IO_8)
PCIE_3V3_EP_PWRBRKN: C19.1 R12.2 R774.1 U5.A10(IO_8)
PCIE_3V3_EP_SMBCLK: J1.B5(SMCLK) R1.1 R3.2 R6944.1 U2.6(SCL)
PCIE_3V3_EP_SMBDAT: J1.B6(SMDAT) R2.1 R4.2 R6945.1 U2.5(SDA)
PCIE_3V3_EP_WAKEN: J1.B11(WAKE_N) R8.1
PCIE_EP_3V3: J1.A9(+3_3V) J1.A10(+3_3V) J1.B8(+3_3V) R1.2 R2.2 R7.2
PCIE_EP_12V: J1.A2(+12V) J1.A3(+12V) J1.B1(+12V) J1.B2(+12V) J1.B3(+12V) ; also on sheet 40
PCIE_EP_JTAG_TCK: J1.A5(JTAG_TCK) ; also on sheet 34
PCIE_EP_JTAG_TDI: J1.A6(JTAG_TDI) ; also on sheet 34
PCIE_EP_JTAG_TDO: J1.A7(JTAG_TDO) ; also on sheet 34
PCIE_EP_JTAG_TMS: J1.A8(JTAG_TMS) ; also on sheet 34
PCIE_EP_PRSNT_N: J1.A1(PRSNT1_N) SW1.1(A1) SW1.2(A2) SW1.3(A3) SW1.4(A4)
PCIE_EP_PRSNT_Nx1: C27.1 J1.B17(PRSNT2n_X1) SW1.5(B4)
PCIE_EP_PRSNT_Nx4: C28.1 J1.B31(PRSNT2n_X4) SW1.6(B3)
PCIE_EP_PRSNT_Nx8: C29.1 J1.B48(PRSNT2n_X8) SW1.7(B2)
PCIE_EP_PRSNT_Nx16: C30.1 J1.B81(PRSNT2n_X16) SW1.8(B1)
PCIE_EP_RX_CN0: C2.2 J1.A17(PER0N)
PCIE_EP_RX_CN1: C7.2 J1.A22(PER1N)
PCIE_EP_RX_CN2: C9.2 J1.A26(PER2N)
PCIE_EP_RX_CN3: C11.2 J1.A30(PER3N)
PCIE_EP_RX_CN4: C13.2 J1.A36(PER4N)
PCIE_EP_RX_CN5: C15.2 J1.A40(PER5N)
PCIE_EP_RX_CN6: C20.2 J1.A44(PER6N)
PCIE_EP_RX_CN7: C26.2 J1.A48(PER7N)
PCIE_EP_RX_CN8: C32.2 J1.A53(PER8N)
PCIE_EP_RX_CN9: C34.2 J1.A57(PER9N)
PCIE_EP_RX_CN10: C36.2 J1.A61(PER10N)
PCIE_EP_RX_CN11: C39.2 J1.A65(PER11N)
PCIE_EP_RX_CN12: C41.2 J1.A69(PER12N)
PCIE_EP_RX_CN13: C43.2 J1.A73(PER13N)
PCIE_EP_RX_CN14: C45.2 J1.A77(PER14N)
PCIE_EP_RX_CN15: C47.2 J1.A81(PER15N)
PCIE_EP_RX_CP0: C1.2 J1.A16(PER0P)
PCIE_EP_RX_CP1: C6.2 J1.A21(PER1P)
PCIE_EP_RX_CP2: C8.2 J1.A25(PER2P)
PCIE_EP_RX_CP3: C10.2 J1.A29(PER3P)
PCIE_EP_RX_CP4: C12.2 J1.A35(PER4P)
PCIE_EP_RX_CP5: C14.2 J1.A39(PER5P)
PCIE_EP_RX_CP6: C18.2 J1.A43(PER6P)
PCIE_EP_RX_CP7: C24.2 J1.A47(PER7P)
PCIE_EP_RX_CP8: C31.2 J1.A52(PER8P)
PCIE_EP_RX_CP9: C33.2 J1.A56(PER9P)
PCIE_EP_RX_CP10: C35.2 J1.A60(PER10P)
PCIE_EP_RX_CP11: C38.2 J1.A64(PER11P)
PCIE_EP_RX_CP12: C40.2 J1.A68(PER12P)
PCIE_EP_RX_CP13: C42.2 J1.A72(PER13P)
PCIE_EP_RX_CP14: C44.2 J1.A76(PER14P)
PCIE_EP_RX_CP15: C46.2 J1.A80(PER15P)
PCIE_EP_RX_N0: C2.1 ; also on sheet 21
PCIE_EP_RX_N1: C7.1 ; also on sheet 21
PCIE_EP_RX_N2: C9.1 ; also on sheet 21
PCIE_EP_RX_N3: C11.1 ; also on sheet 21
PCIE_EP_RX_N4: C13.1 ; also on sheet 21
PCIE_EP_RX_N5: C15.1 ; also on sheet 21
PCIE_EP_RX_N6: C20.1 ; also on sheet 21
PCIE_EP_RX_N7: C26.1 ; also on sheet 21
PCIE_EP_RX_N8: C32.1 ; also on sheet 21
PCIE_EP_RX_N9: C34.1 ; also on sheet 21
PCIE_EP_RX_N10: C36.1 ; also on sheet 21
PCIE_EP_RX_N11: C39.1 ; also on sheet 21
PCIE_EP_RX_N12: C41.1 ; also on sheet 21
PCIE_EP_RX_N13: C43.1 ; also on sheet 21
PCIE_EP_RX_N14: C45.1 ; also on sheet 21
PCIE_EP_RX_N15: C47.1 ; also on sheet 21
PCIE_EP_RX_P0: C1.1 ; also on sheet 21
PCIE_EP_RX_P1: C6.1 ; also on sheet 21
PCIE_EP_RX_P2: C8.1 ; also on sheet 21
PCIE_EP_RX_P3: C10.1 ; also on sheet 21
PCIE_EP_RX_P4: C12.1 ; also on sheet 21
PCIE_EP_RX_P5: C14.1 ; also on sheet 21
PCIE_EP_RX_P6: C18.1 ; also on sheet 21
PCIE_EP_RX_P7: C24.1 ; also on sheet 21
PCIE_EP_RX_P8: C31.1 ; also on sheet 21
PCIE_EP_RX_P9: C33.1 ; also on sheet 21
PCIE_EP_RX_P10: C35.1 ; also on sheet 21
PCIE_EP_RX_P11: C38.1 ; also on sheet 21
PCIE_EP_RX_P12: C40.1 ; also on sheet 21
PCIE_EP_RX_P13: C42.1 ; also on sheet 21
PCIE_EP_RX_P14: C44.1 ; also on sheet 21
PCIE_EP_RX_P15: C46.1 ; also on sheet 21
PCIE_EP_TX_N0: J1.B15(PET0N) ; also on sheet 21
PCIE_EP_TX_N1: J1.B20(PET1N) ; also on sheet 21
PCIE_EP_TX_N2: J1.B24(PET2N) ; also on sheet 21
PCIE_EP_TX_N3: J1.B28(PET3N) ; also on sheet 21
PCIE_EP_TX_N4: J1.B34(PET4N) ; also on sheet 21
PCIE_EP_TX_N5: J1.B38(PET5N) ; also on sheet 21
PCIE_EP_TX_N6: J1.B42(PET6N) ; also on sheet 21
PCIE_EP_TX_N7: J1.B46(PET7N) ; also on sheet 21
PCIE_EP_TX_N8: J1.B51(PET8N) ; also on sheet 21
PCIE_EP_TX_N9: J1.B55(PET9N) ; also on sheet 21
PCIE_EP_TX_N10: J1.B59(PET10N) ; also on sheet 21
PCIE_EP_TX_N11: J1.B63(PET11N) ; also on sheet 21
PCIE_EP_TX_N12: J1.B67(PET12N) ; also on sheet 21
PCIE_EP_TX_N13: J1.B71(PET13N) ; also on sheet 21
PCIE_EP_TX_N14: J1.B75(PET14N) ; also on sheet 21
PCIE_EP_TX_N15: J1.B79(PET15N) ; also on sheet 21
PCIE_EP_TX_P0: J1.B14(PET0P) ; also on sheet 21
PCIE_EP_TX_P1: J1.B19(PET1P) ; also on sheet 21
PCIE_EP_TX_P2: J1.B23(PET2P) ; also on sheet 21
PCIE_EP_TX_P3: J1.B27(PET3P) ; also on sheet 21
PCIE_EP_TX_P4: J1.B33(PET4P) ; also on sheet 21
PCIE_EP_TX_P5: J1.B37(PET5P) ; also on sheet 21
PCIE_EP_TX_P6: J1.B41(PET6P) ; also on sheet 21
PCIE_EP_TX_P7: J1.B45(PET7P) ; also on sheet 21
PCIE_EP_TX_P8: J1.B50(PET8P) ; also on sheet 21
PCIE_EP_TX_P9: J1.B54(PET9P) ; also on sheet 21
PCIE_EP_TX_P10: J1.B58(PET10P) ; also on sheet 21
PCIE_EP_TX_P11: J1.B62(PET11P) ; also on sheet 21
PCIE_EP_TX_P12: J1.B66(PET12P) ; also on sheet 21
PCIE_EP_TX_P13: J1.B70(PET13P) ; also on sheet 21
PCIE_EP_TX_P14: J1.B74(PET14P) ; also on sheet 21
PCIE_EP_TX_P15: J1.B78(PET15P) ; also on sheet 21
PCIE_HSC_ALERT_N: U5.A12(IO_8) ; also on sheet 40
PCIE_HSC_PG: U5.B11(IO_8) ; also on sheet 40
PCIE_RSV2: C17.1 J1.A19(RSVD2)
PCIE_RSV4: C21.1 J1.A32(RSVD4)
PCIE_RSV5: C22.1 J1.A33(RSVD5)
PCIE_RSV6: C23.1 J1.B82(RSVD6)
PCIE_RSV7: C25.1 J1.A50(RSVD7)
PTP_CLK_RST_N: U5.J2(IO_1B) ; also on sheet 32
PWRGD_G0: U5.H12(IO_6) ; also on sheet 41
PWRGD_G1: U5.G14(IO_6) ; also on sheet 49
PWRGD_G2: U5.G16(IO_6) ; also on sheet 50
PWRGD_G3: U5.G15(IO_6) ; also on sheet 53
PWRGD_OUT: U5.F16(IO_6) ; also on sheet 36
QSFP_3V3_MODPRS_L: U5.P2(IO_3) ; also on sheet 16 30
QSFP_FAULT_N: U5.C14(IO_6_C14/PLL_R_CLKOUTN) ; also on sheet 30
QSFP_PWR_EN: U5.D15(IO_6) ; also on sheet 30
QSFPDD_3V3_MODPRS_L: U5.P4(IO_3) ; also on sheet 16 29
QSFPDD_FAULT_N: U5.D14(IO_6_D14/PLL_R_CLKOUTP) ; also on sheet 29
QSFPDD_PWR_EN: U5.E16(IO_6) ; also on sheet 29
REFCLK_PCIE_EP_EDGE_N: J1.A14(REFCLK-) ; also on sheet 33
REFCLK_PCIE_EP_EDGE_P: J1.A13(REFCLK+) ; also on sheet 33
SVID_ENABLE: U5.C9(IO_8_C9/CLK4N) ; also on sheet 35
TEMP1_THERMn: U5.G12(IO_6_G12/DPCLK2) ; also on sheet 34
TEMP2_THERMn: U5.C15(IO_6) ; also on sheet 34
USB_DISABLEn: R86.2 R88.2 U5.J14(IO_6) ; also on sheet 38
USB_MAX_JTAG_SEL: R87.2 R90.1 SW2.1(A1) U5.H15(IO_6) U6.15(IN)
USB_MAX_TCK: U5.H3(IO_1B_H3/TCK) U6.2(COM1)
USB_MAX_TDI: U5.G1(IO_1B_G1/TDI) U6.7(COM3)
USB_MAX_TDO: U5.H1(IO_1B_H1TDO) U6.10(COM4)
USB_MAX_TMS: U5.H2(IO_1B_H2/TMS) U6.5(COM2)
USB_T_CLK: U5.P9(IO_3_P9/CLK6N) ; also on sheet 38
ZL_GPIO3_AC3: U5.B7(IO_8) ; also on sheet 32
N614425: J1.B9(JTAG_TRSTN) R5.1 R7.1
N615469: J1.B30(RSVD3) R774.2
N615809: C16.2 R13.1
N615921: C17.2 R14.1
N616003: C19.2 R15.1
N616075: C21.2 R16.1
N616149: C22.2 R17.1
N616261: C23.2 R18.1
N616323: C25.2 R19.1
N616411: C27.2 R20.1
N616501: C28.2 R21.1
N616597: C29.2 R22.1
N616647: C30.2 R23.1
N617181: R24.1 R30.2 U2.3(A2)
N617185: R25.1 R31.2 U2.2(A1)
N617189: R26.1 R29.2 U2.1(A0)
N617309: R27.1 R28.2 U2.7(WP)
N899386: R93.1 U7.3(OUT)
N2166287: D1.C(CATHODE) Q1.3(DRAIN)
N2166291: D1.A(ANODE) R82.1
N2746722: J2.3(TACH) R89.1
N2830778: R79.1 U5.A8(IO_8)
N2830869: R69.2 U5.J11(IO_6_J11/CLK2P)
N2830873: R70.2 U5.J12(IO_6_J12/CLK2N)
N2830995: R52.1 U5.H5(IO_1A_H5/ADC1IN3)
N2830997: R54.1 U5.B2(IO_1A_B2/ADC2IN6)
N2831098: R53.1 U5.N2(IO_2_N2/DPCLK0)
N2831570: R71.1 U5.K14(IO_5)
N6052446: J3.2 R88.1

Not connected (* = marked no-connect by the designer): J3 7* 8*; U3 A2(DNU1)* A3(DNU2)* A5(DNU3)* B1(DNU4)* B5(DNU5)* C1(DNU6)* C3(DNU7)* C5(DNU8)* D1(DNU9)* D5(DNU10)* E1(DNU11)* E2(DNU12)* E3(DNU13)* E4(DNU14)* E5(DNU15)*; U4 A2(DNU1)* A3(DNU2)* A5(DNU3)* B1(DNU4)* B5(DNU5)* C1(DNU6)* C3(DNU7)* C5(DNU8)* D1(DNU9)* D5(DNU10)* E1(DNU11)* E2(DNU12)* E3(DNU13)* E4(DNU14)* E5(DNU15)*; U5 A14(IO_7)* A15(IO_7_A15/VREFB7N0)* B8(IO_8_B8/DEV_OE)* B10(IO_8_B10/DEV_CLRN)* B13(IO_7)* E4(ADC_VREF)* E9(IO_8_E9/CLK5N)* E10(IO_7)* F9(IO_8_F9/CLK5P)* F10(IO_7)* F11(IO_7)* F12(IO_7)*

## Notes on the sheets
sheet 1
- REV
- DATE
- PAGES
- DESCRIPTION
- A1
- 06/29/2021
- All
- Preliminary Release for checking
- B1
- 01/03/2022
- Pg53
- Pg58
- Change U77,U78 pin7 EN connection to 3V3_STBY
- Swap MAX_I2C_SCL/SDA connection on U93
- Pg54
- Swap MAX_I2C_SCL/SDA connection on U96
- Pg1
- Correct Table of Contents, Pg20, Pg21
- Pg2
- Update Block Diagram:  Remove Reference to U20-12C and U12-13A
- C1
- 03/19/2024
- PAGE
- DESCRIPTION
- PAGE
- DESCRIPTION
- 1
- Cover, Table of Contents, Notes
- 38
- I2C Translators
- 2
- Block Diagram
- 39
- Buttons, Switches, LEDs
- 3
- Power Tree Diagram
- 40
- EEPROM, NIOS Flash
- 4
- Clock Diagram
- 41
- USB-Blaster II, JTAG
- 5
- I2C Diagram
- 42
- FPGA Decoupling
- 6
- JTAG Diagram
- 43
- Input Power HSC
- 7
- Power Sequence Diagram
- 44
- 5V0, MAX: 2V5, 1V8, 1V2
- 8
- PCIE Edge Finger
- 45
- 3V3_STBY, 3V3_SYS
- 9
- FPGA Configuration Flash
- 46
- VCC Controller
- 10
- Max10 System Controller
- 47
- VCC Phase 1
- 11
- Agilex SDM
- 48
- VCC Phase 2
- 12
- Agilex Bank 2C - DDR4 DIMM1
- 49
- VCC Phase 3
- 13
- Agilex Bank 2D - DDR4 DIMM1
- 50
- VCC Phase 4
- 14
- Agilex Bank 2E - DDR4 DIMM2
- 51
- VCC_HSSI_GXF Phase 5
- 15
- Agilex Bank 2F - DDR4 DIMM2
- 52
- VCCH_SDM
- 16
- Agilex Bank 3A - General IO's
- 53
- VCCERT_FGT_GXF
- 17
- Agilex Bank 3B - Unused IO's
- 54
- VCCPT, VCCFUSEWR_GXF
- 18
- Agilex Bank 3C - Unused IO's
- 55
- VCCR_CORE
- 19
- Agilex Bank 3D - DDR4 Component
- 56
- VCCIO_1V2
- 20
- Agilex F-Tile Bank 13A - PCIE Gen4x16
- 57
- VCCIO_SDM, VCCFUSEWR_SDM
- 21
- Agilex F-Tile Bank 12C - QSFPDD, QSFP, CXL
- 58
- PG58 2V5_DDR4, DDR4 VTT, VREF
- 22
- Agilex HPS, TEMPDIODE, DNU
- 23
- Agilex Power
- 24
- Agilex GND
- 25
- DDR4 / DDR-T Pin Mapping
- 26
- DDR4 / DDR-T DIMM1
- 27
- DDR4 / DDR-T DIMM2
- 28
- HPS DDR4 COMP 1 & 2
- 29
- HPS DDR4 COMP 3 & 4
- 30
- HPS DDR4 COMP 5, TERMINATION
- 31
- HPS IO48 Interface
- 32
- QSFPDD-56
- 33
- QSFP-56
- 34
- CXL Connector
- 35
- Clock 1 - IEEE 1588 Clocking
- 36
- Clock 2 - PCIE, CXL Refclocks
- 37
- Buffers, Translators
- SPEED TOP Number - 99ARL0 / 99ARL1 / 99ARL2
    Top Assembly   - M60066-001
      PCB Assembly - M46634-100
        Schematic       - 180-0330678-B1
        FM86/76 Raw PCB - 100-0330678-B1
        Gerbers         - 110-0330678-B1
- AGILEX FPGA (PROD) P/N:  AGFB027R24C2E2V (MMID: TBD)
- AGILEX FPGA (ES) P/N:  AGFB027R24C2E2VR0  (MMID: 99AKGJ)
- DIMM P/N:  Micron MTA18ASF2G72PZ-3G2J3 (K55448-002)
sheet 8
- PCIe Endpoint Edge Connector
- 3.3V +/-9%
- 375mA max
- Pullups on
  Host PCIE
- Notes: Close --> select;
         Open --> deselect
- PCIe TX/RX signal naming convention
  with respect to CPU
- PCIE TX to FPGA RX
  P/N Lane Reversal during layout is allowed
- PCIE RX from FPGA TX
  P/N Lane Reversal during layout is allowed
- When PWRBRKn is asserted, MAX10 can
  reduce power by clearing FPGA
  proramming and stopping all clocks.
  When PWRBRKn is deasserted, MAX10
  can reconigure FPGA and re-enable
  all clocks.
- Note: Place near to golden finger
- FRUID
- Pull-ups on PG35
- Addr = A0h
- 400Khz max
sheet 9
- QSPI Flash for FPGA Image
- AGILEX AGF027 Bit Stream size = 833.4Mbits
  total FPGA image support = 4
- 2Gbit Flash
- 2Gbit Flash
- 1.7-2.0V
  Absmax = 4V
- 1.7-2.0V
  Absmax = 4V
- These are dual-die flash so each device is 2 loads on MAX10 IOs
sheet 10
- 3.3V Signals
- HPS_COLD_RESETn must be
  bi-directional
  Drive 0 for 5ms to issue HPS RESET
- 1.8V Signals
- 1.8V Signals
- HPS JTAG
  Pull-ups on
  Daughter Card
- 1.2V Signals
- Pull-ups on PG41
- Pull-ups on PG39
- Open Drain
- 3.3V Signals
- 1.8V Signals
- MSEL0
  always '1'
- MAX10 must shut down
  FPGA if CATTRIPn = 0
- Pull-ups on PG35
- 1.2V
- 3.3V Signals
- I2C:
  AbsMax = 4.12V
  Vih_min = 1.7V
  Vil_max = 0.8V
- 1.2V Signals
- Open Drain
- FLASH_IMAGE_SEL[1:0]
  ---------------------
  00 = Flash0, Image0 (Default)
  01 = Flash0, Image1
  10 = Flash1, Image2
  11 = Flash1, Image3
- 3.3V Signals
- 1.8V Signals
- 3.3V Signals
- ZL_GPIO3_AC3 signal
  must be tri-state
  when ZL Clock is
  reset
- Place 1 per VCCIO pin
- Open Drain
- Pull-up on pg44
- VGS(th) = 0.6V / 1V /1.5V
- Place 1 per VCCD pin
- Place 1 per VCCA pin
- For Production: NC <--> COM
  DNI R43, DNI SW2
  INSTALL R45
- IN Lo  = NC <--> COM
  IN Hi = NO <--> COM
- 1.2V Signals
- (TCK)
- (TMS)
- (TDI)
- (TDO)
- External JTAG  Header
- IN = "0"   NC <--> COM
  IN = "1"   NO <--> COM
- USB_MAX_JTAG = "1", Debug mode.
  EXT UBII is disabled on SYS MAX10.
